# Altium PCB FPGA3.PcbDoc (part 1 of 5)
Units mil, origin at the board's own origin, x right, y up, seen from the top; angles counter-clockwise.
Board outline 4000 x 2750 mil, 12 copper layers (Top Layer, Plane1, MidLayer1, Plane2, MidLayer2, Plane3, Plane4, MidLayer 3, Plane5, MidLayer 4, Plane6, Bottom Layer), stack 57.29 mil thick; 420 components, 368 nets, 1889 pads, 1236 vias.
Unrouted connection lines stored in the file: 1.
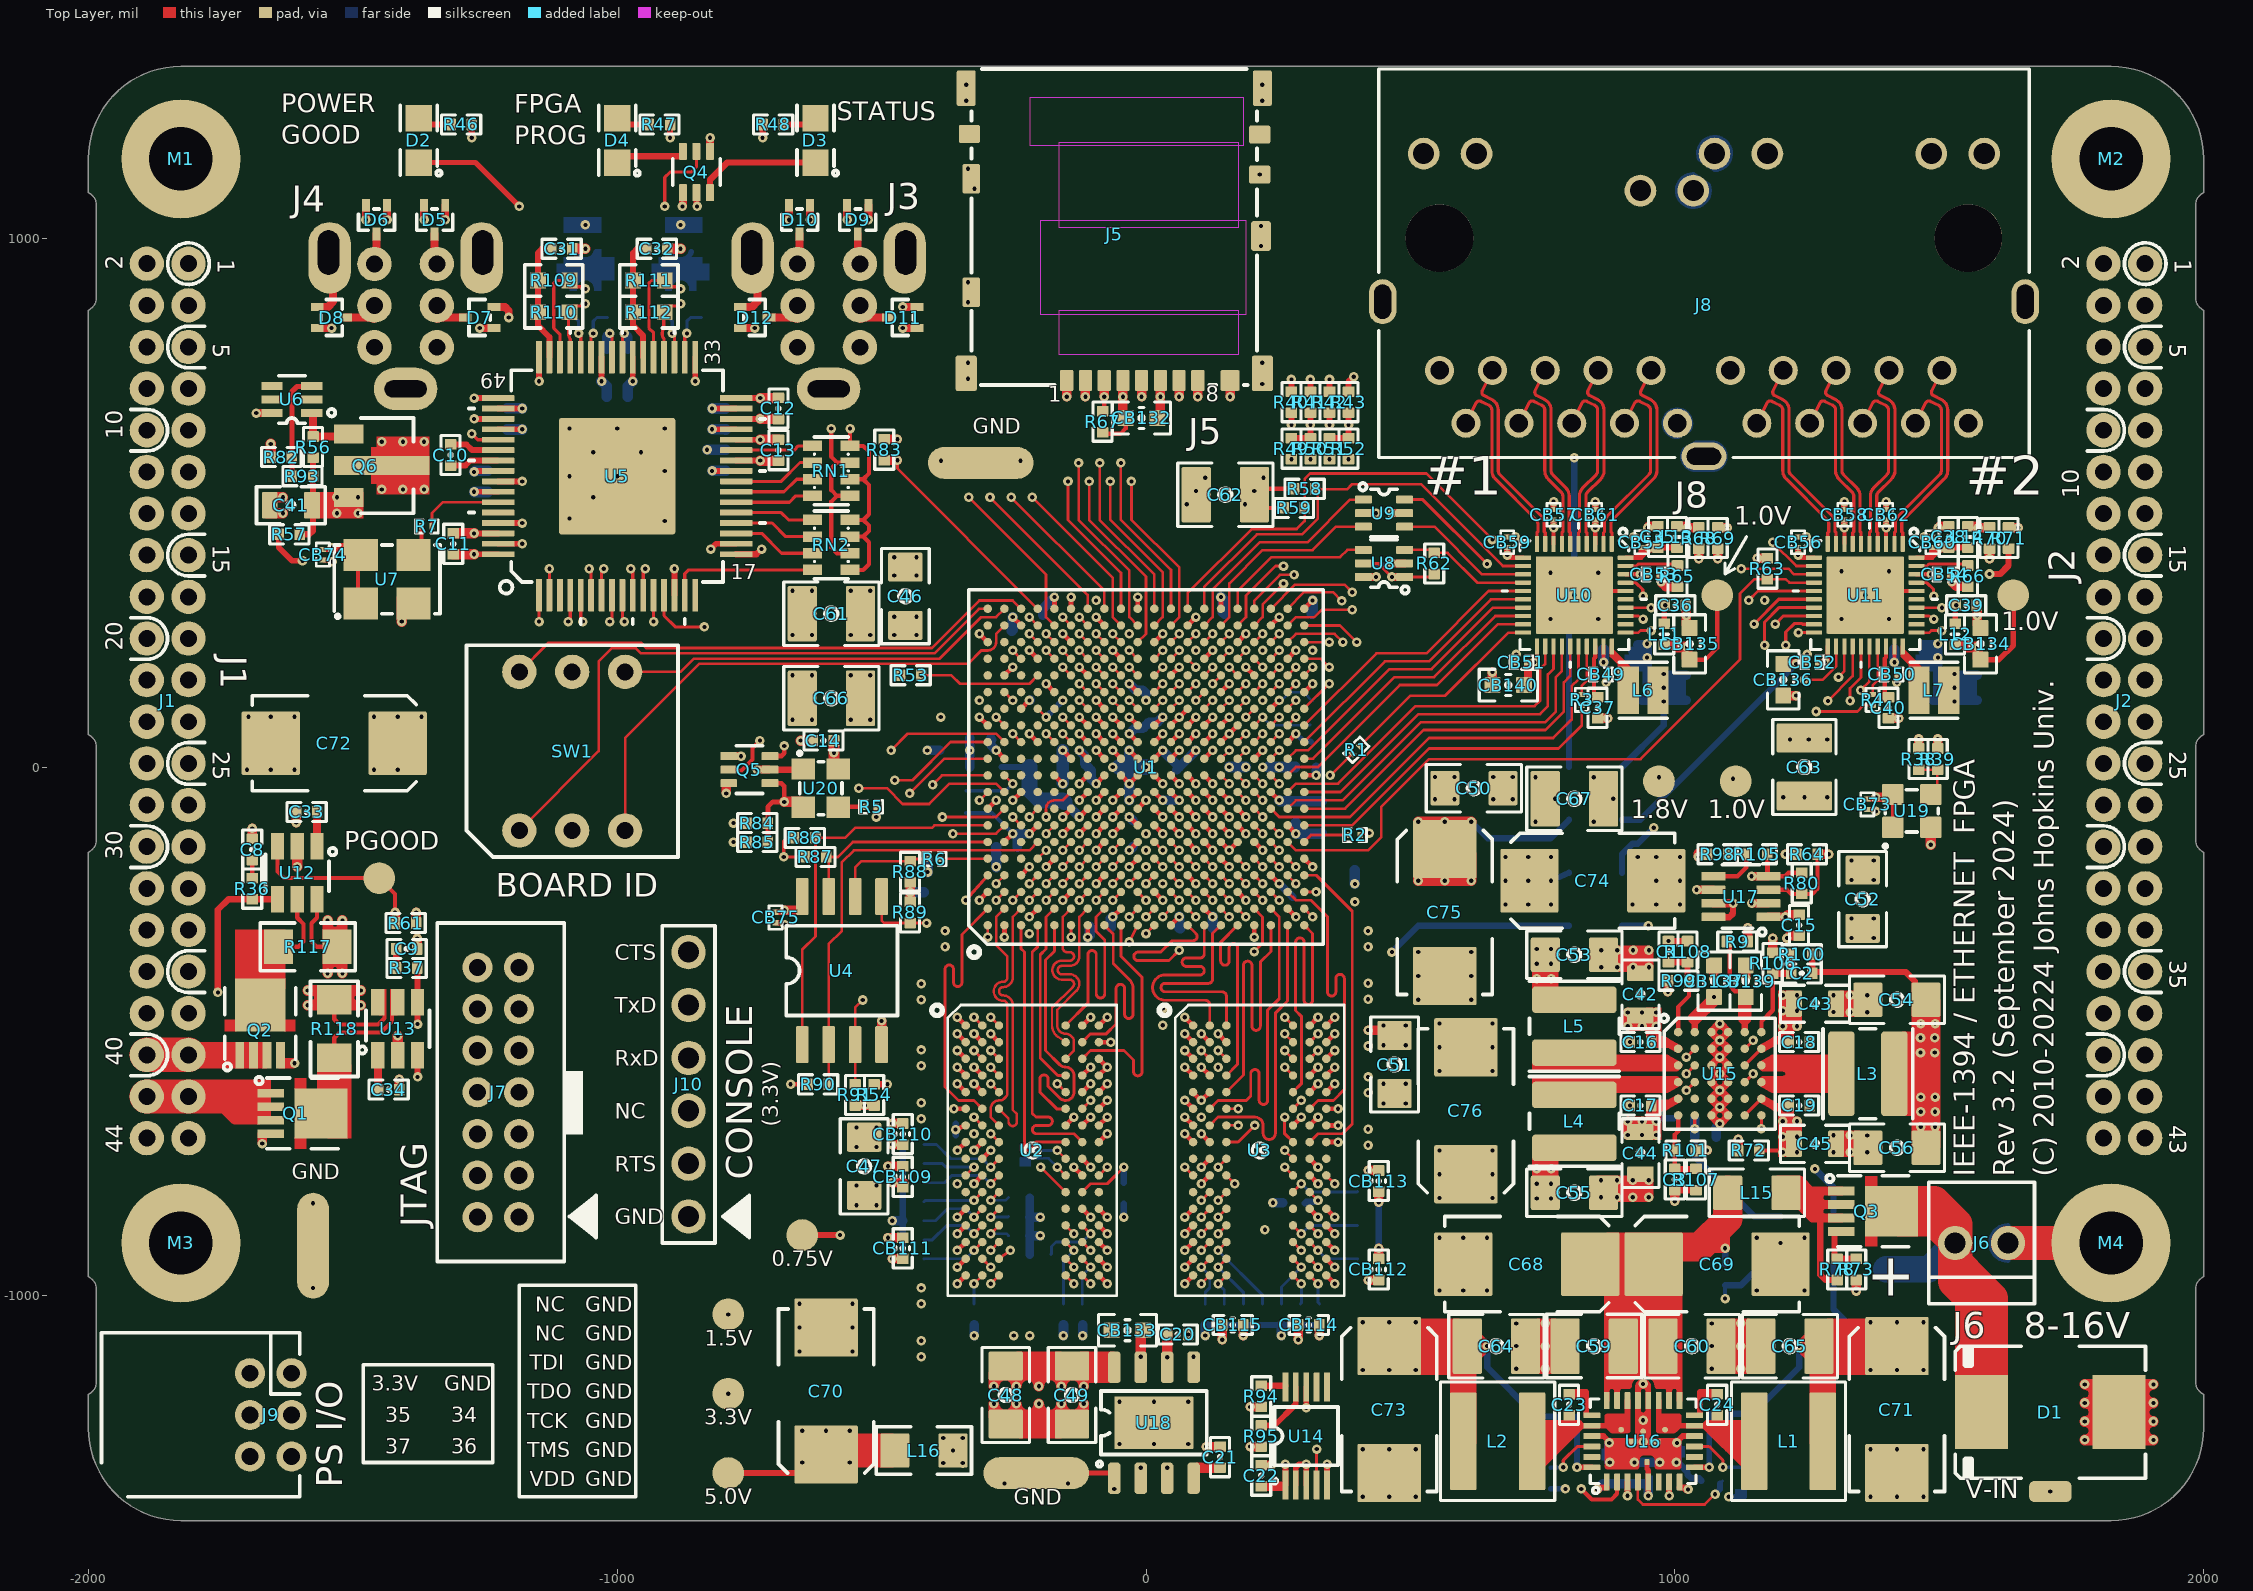
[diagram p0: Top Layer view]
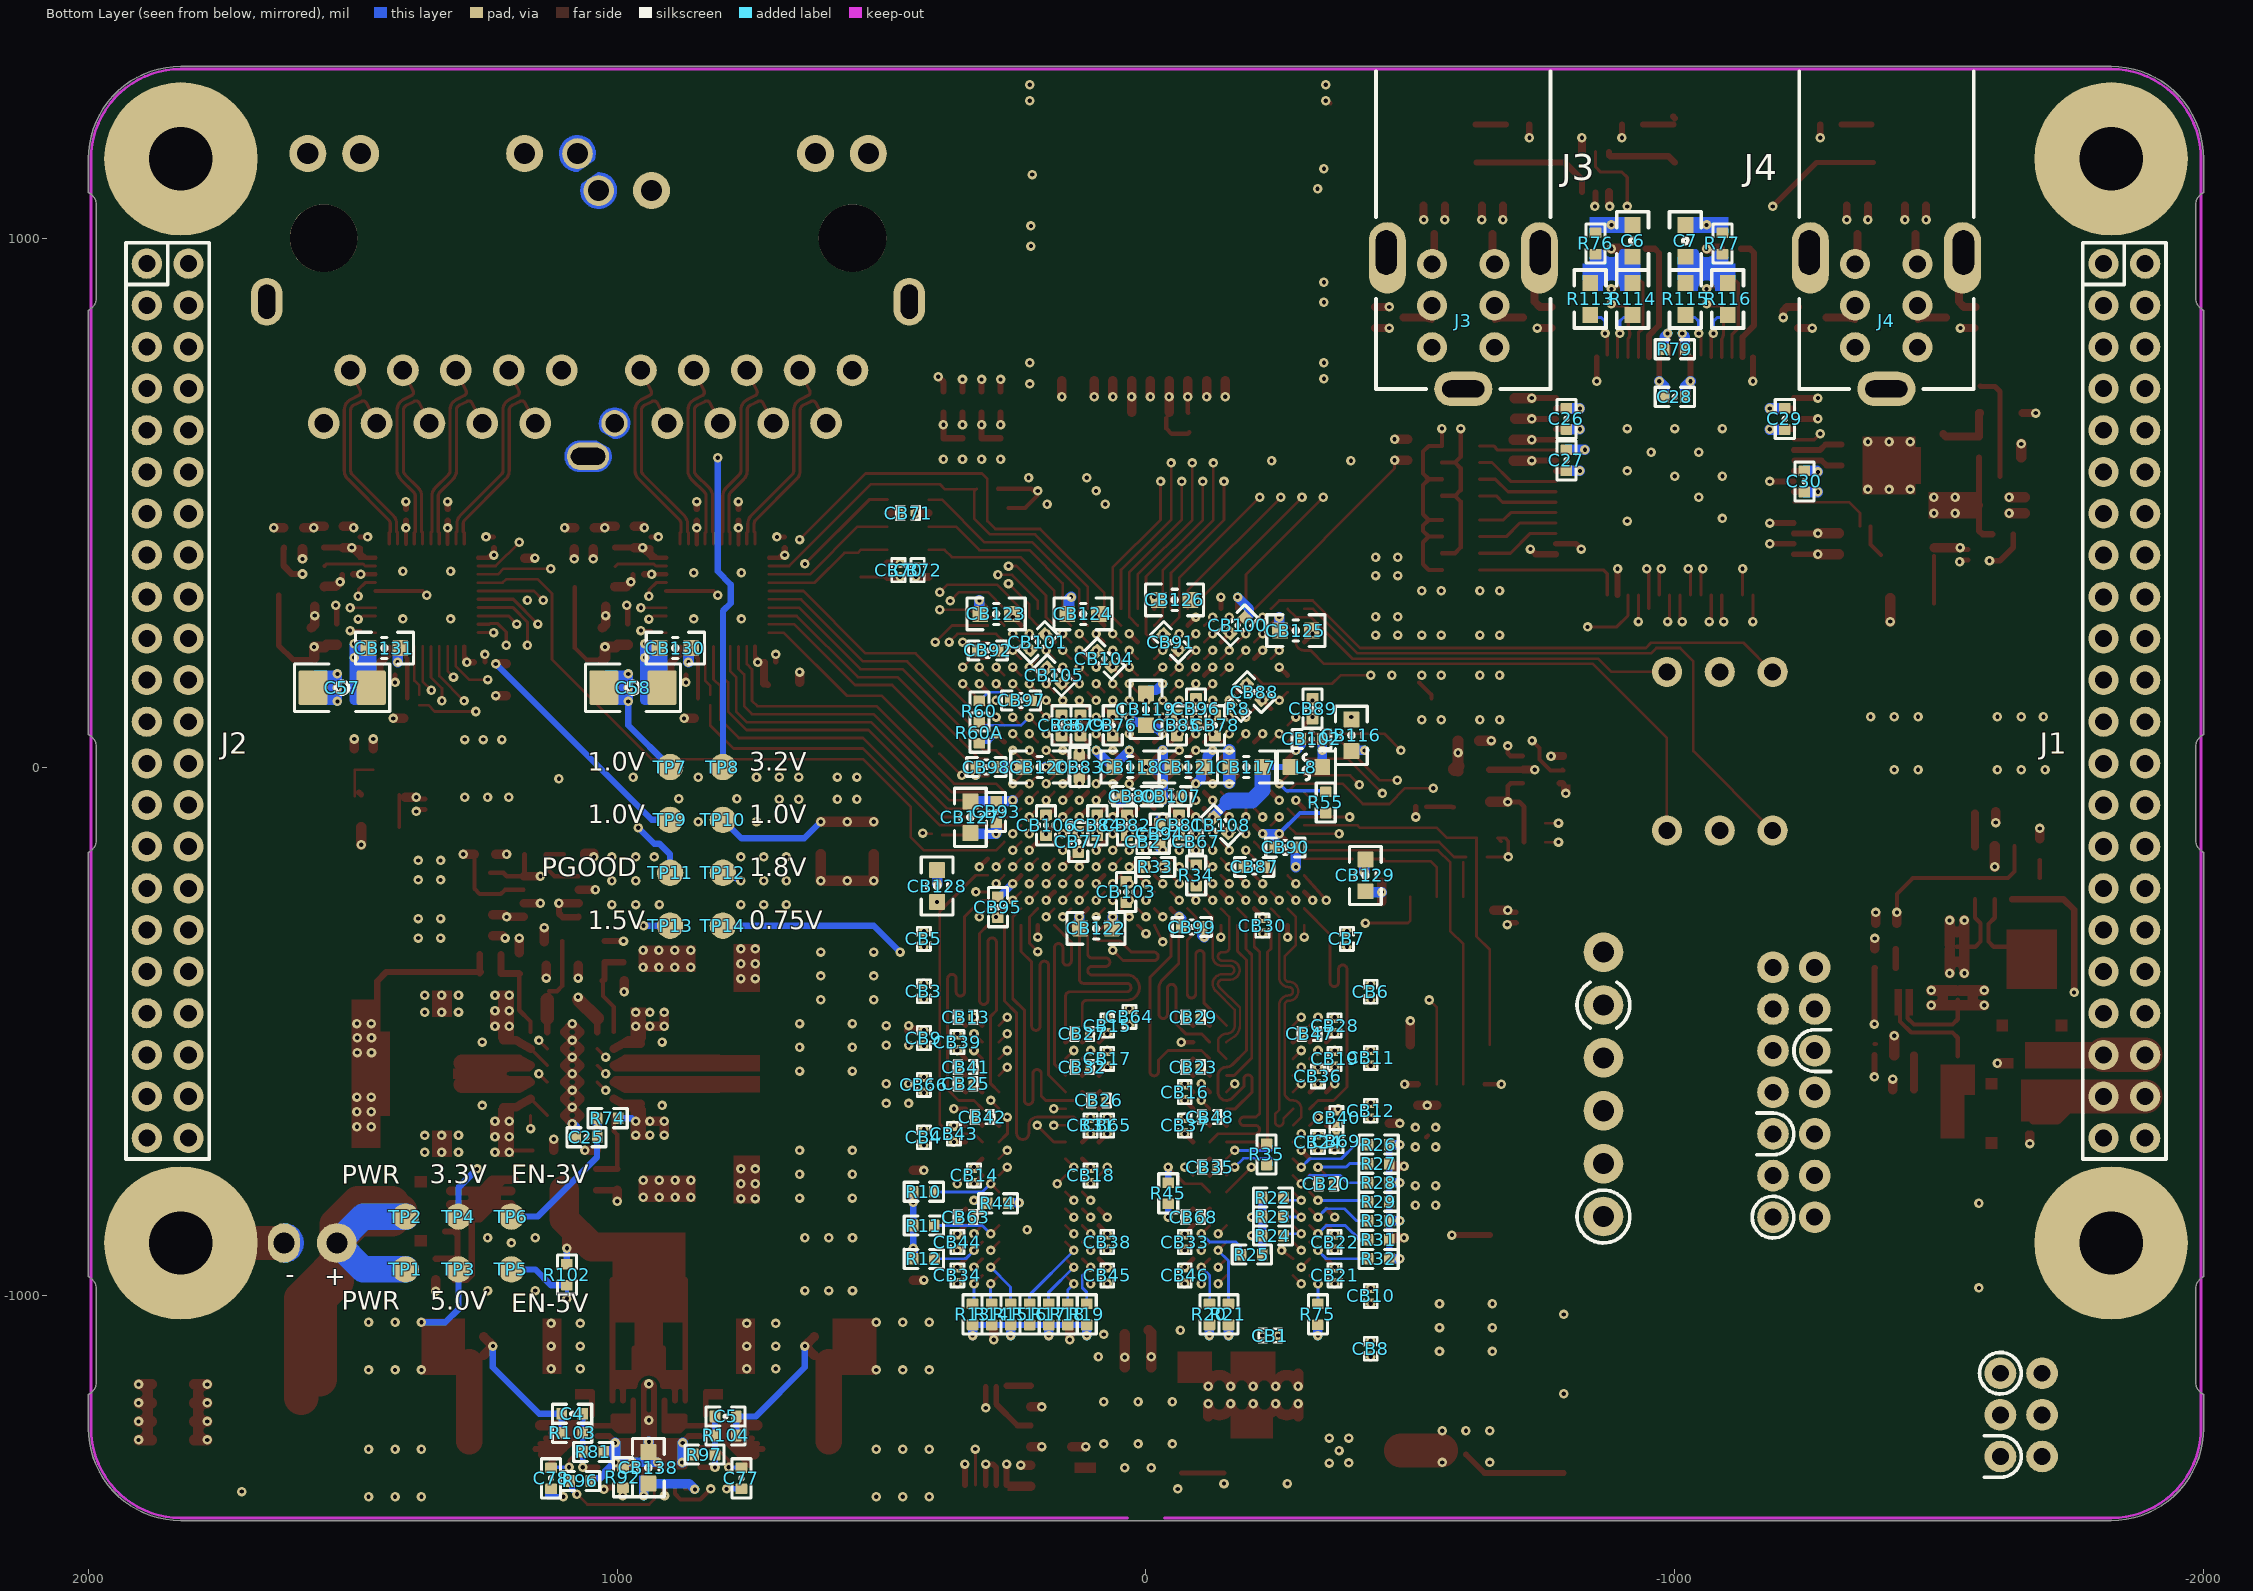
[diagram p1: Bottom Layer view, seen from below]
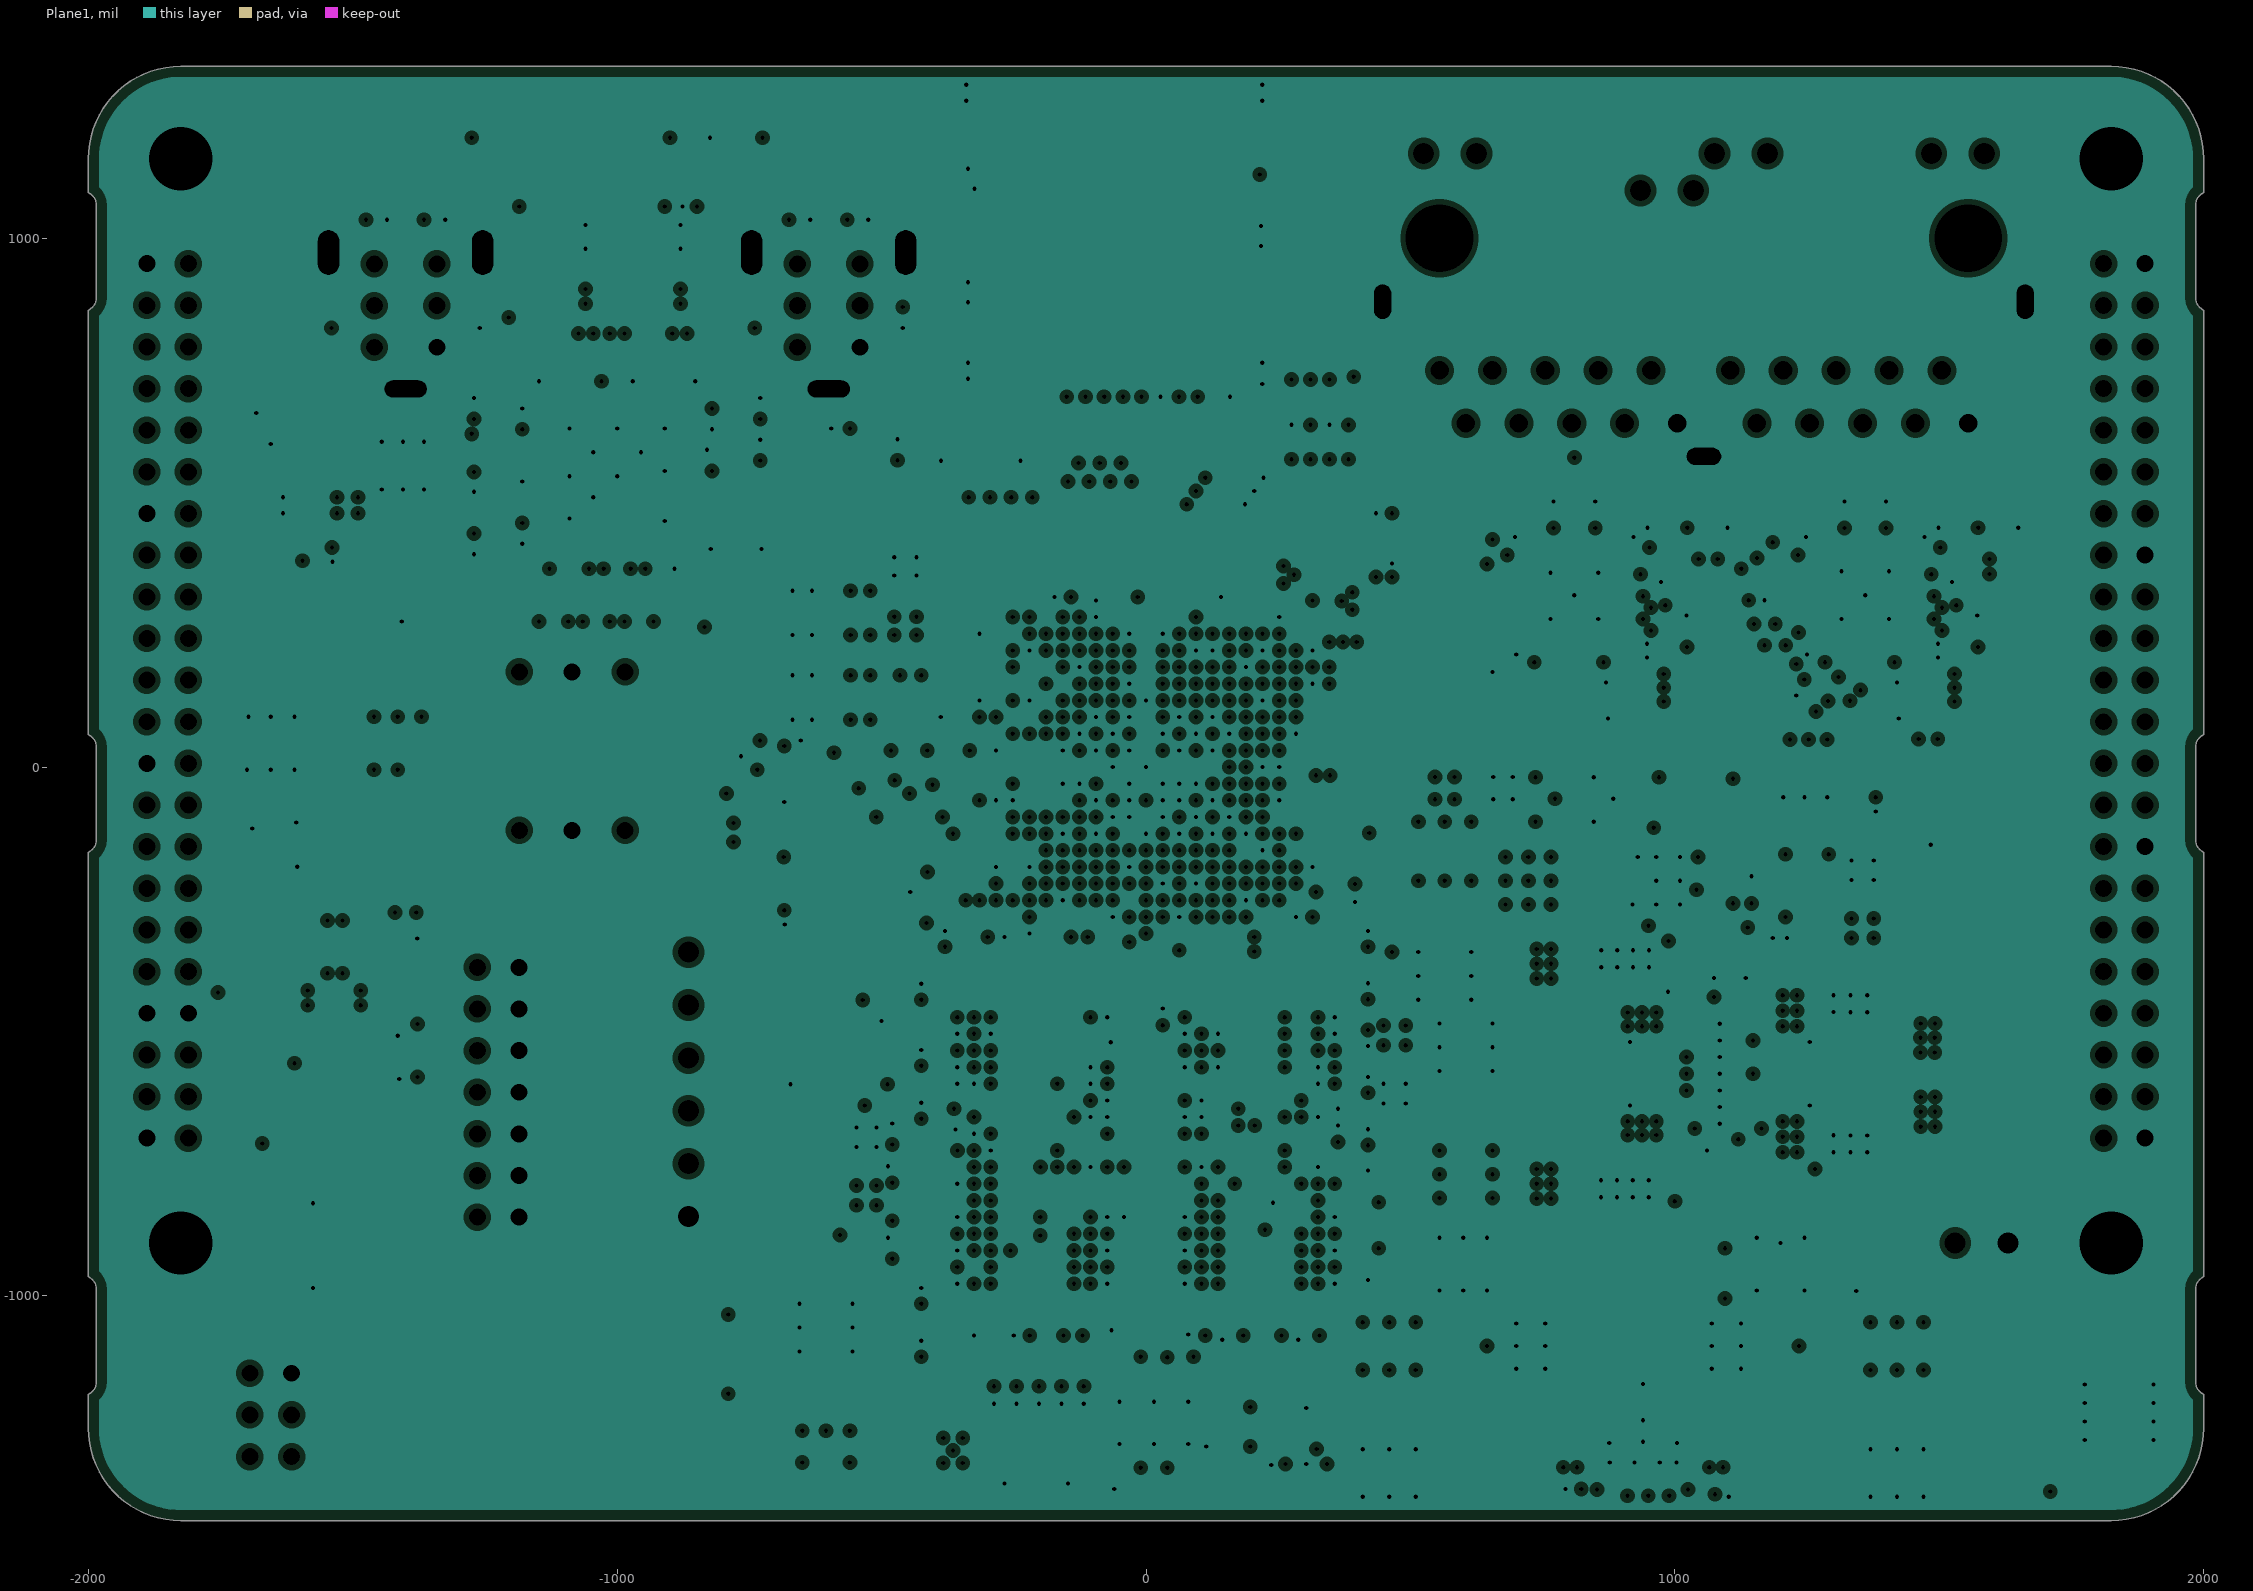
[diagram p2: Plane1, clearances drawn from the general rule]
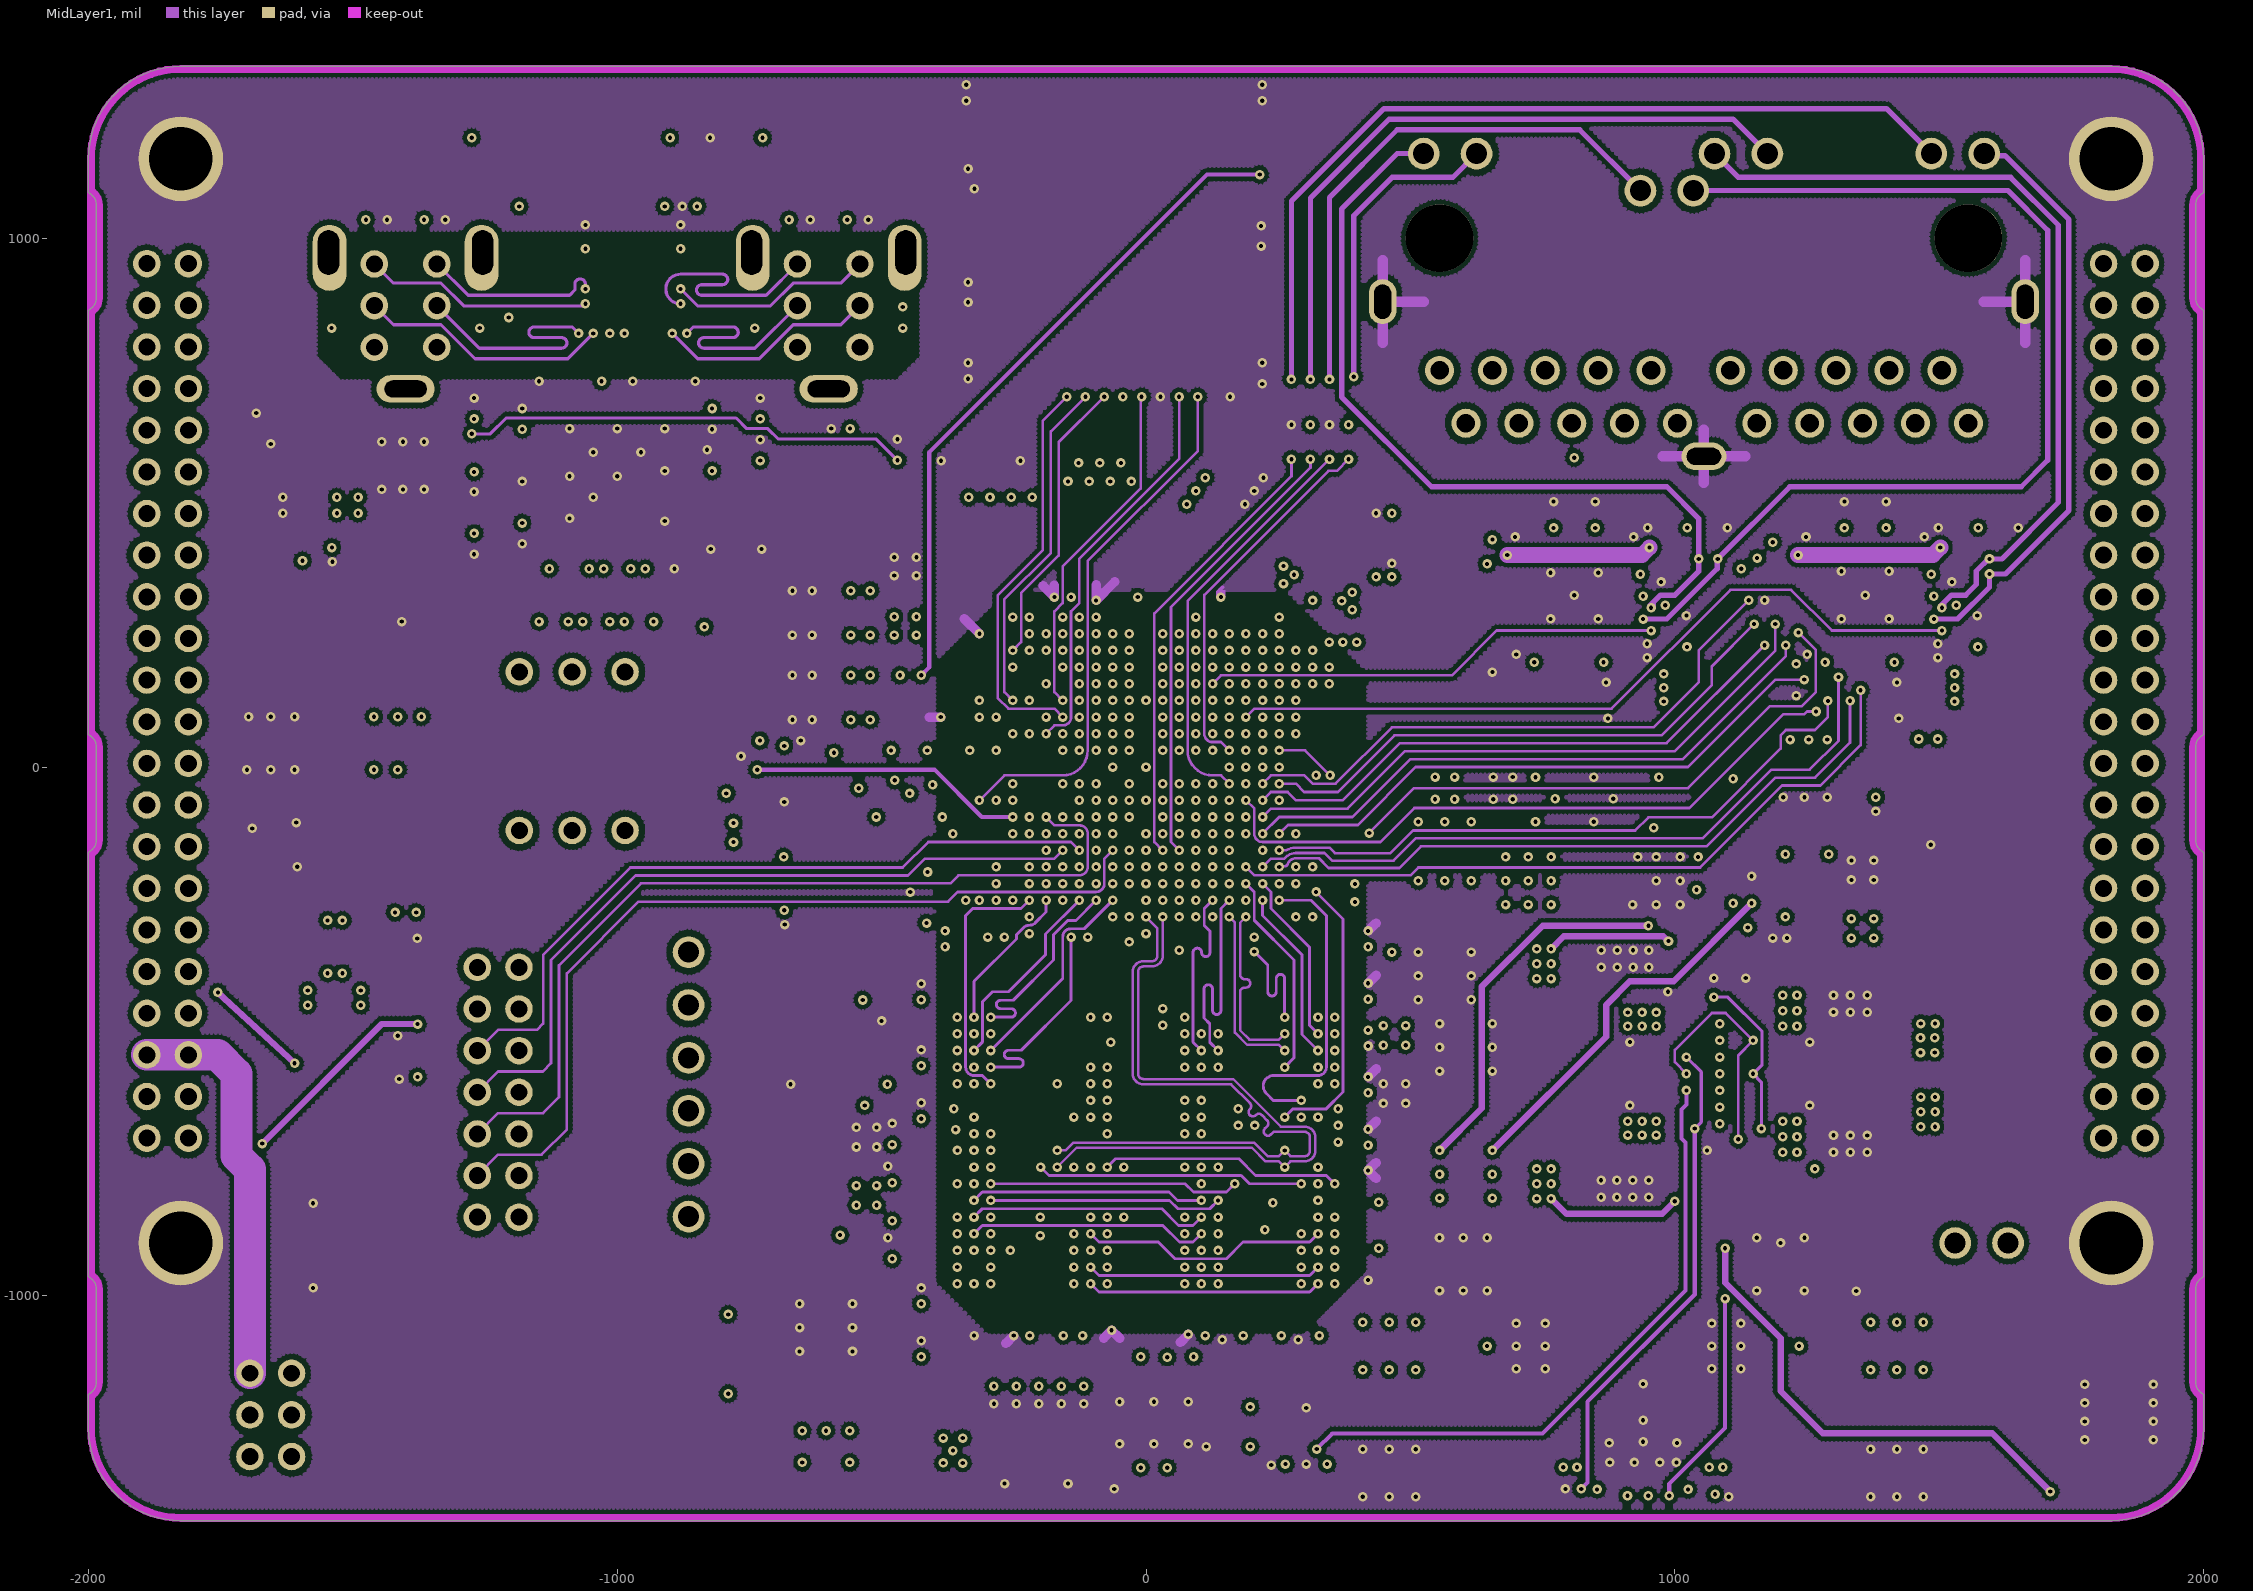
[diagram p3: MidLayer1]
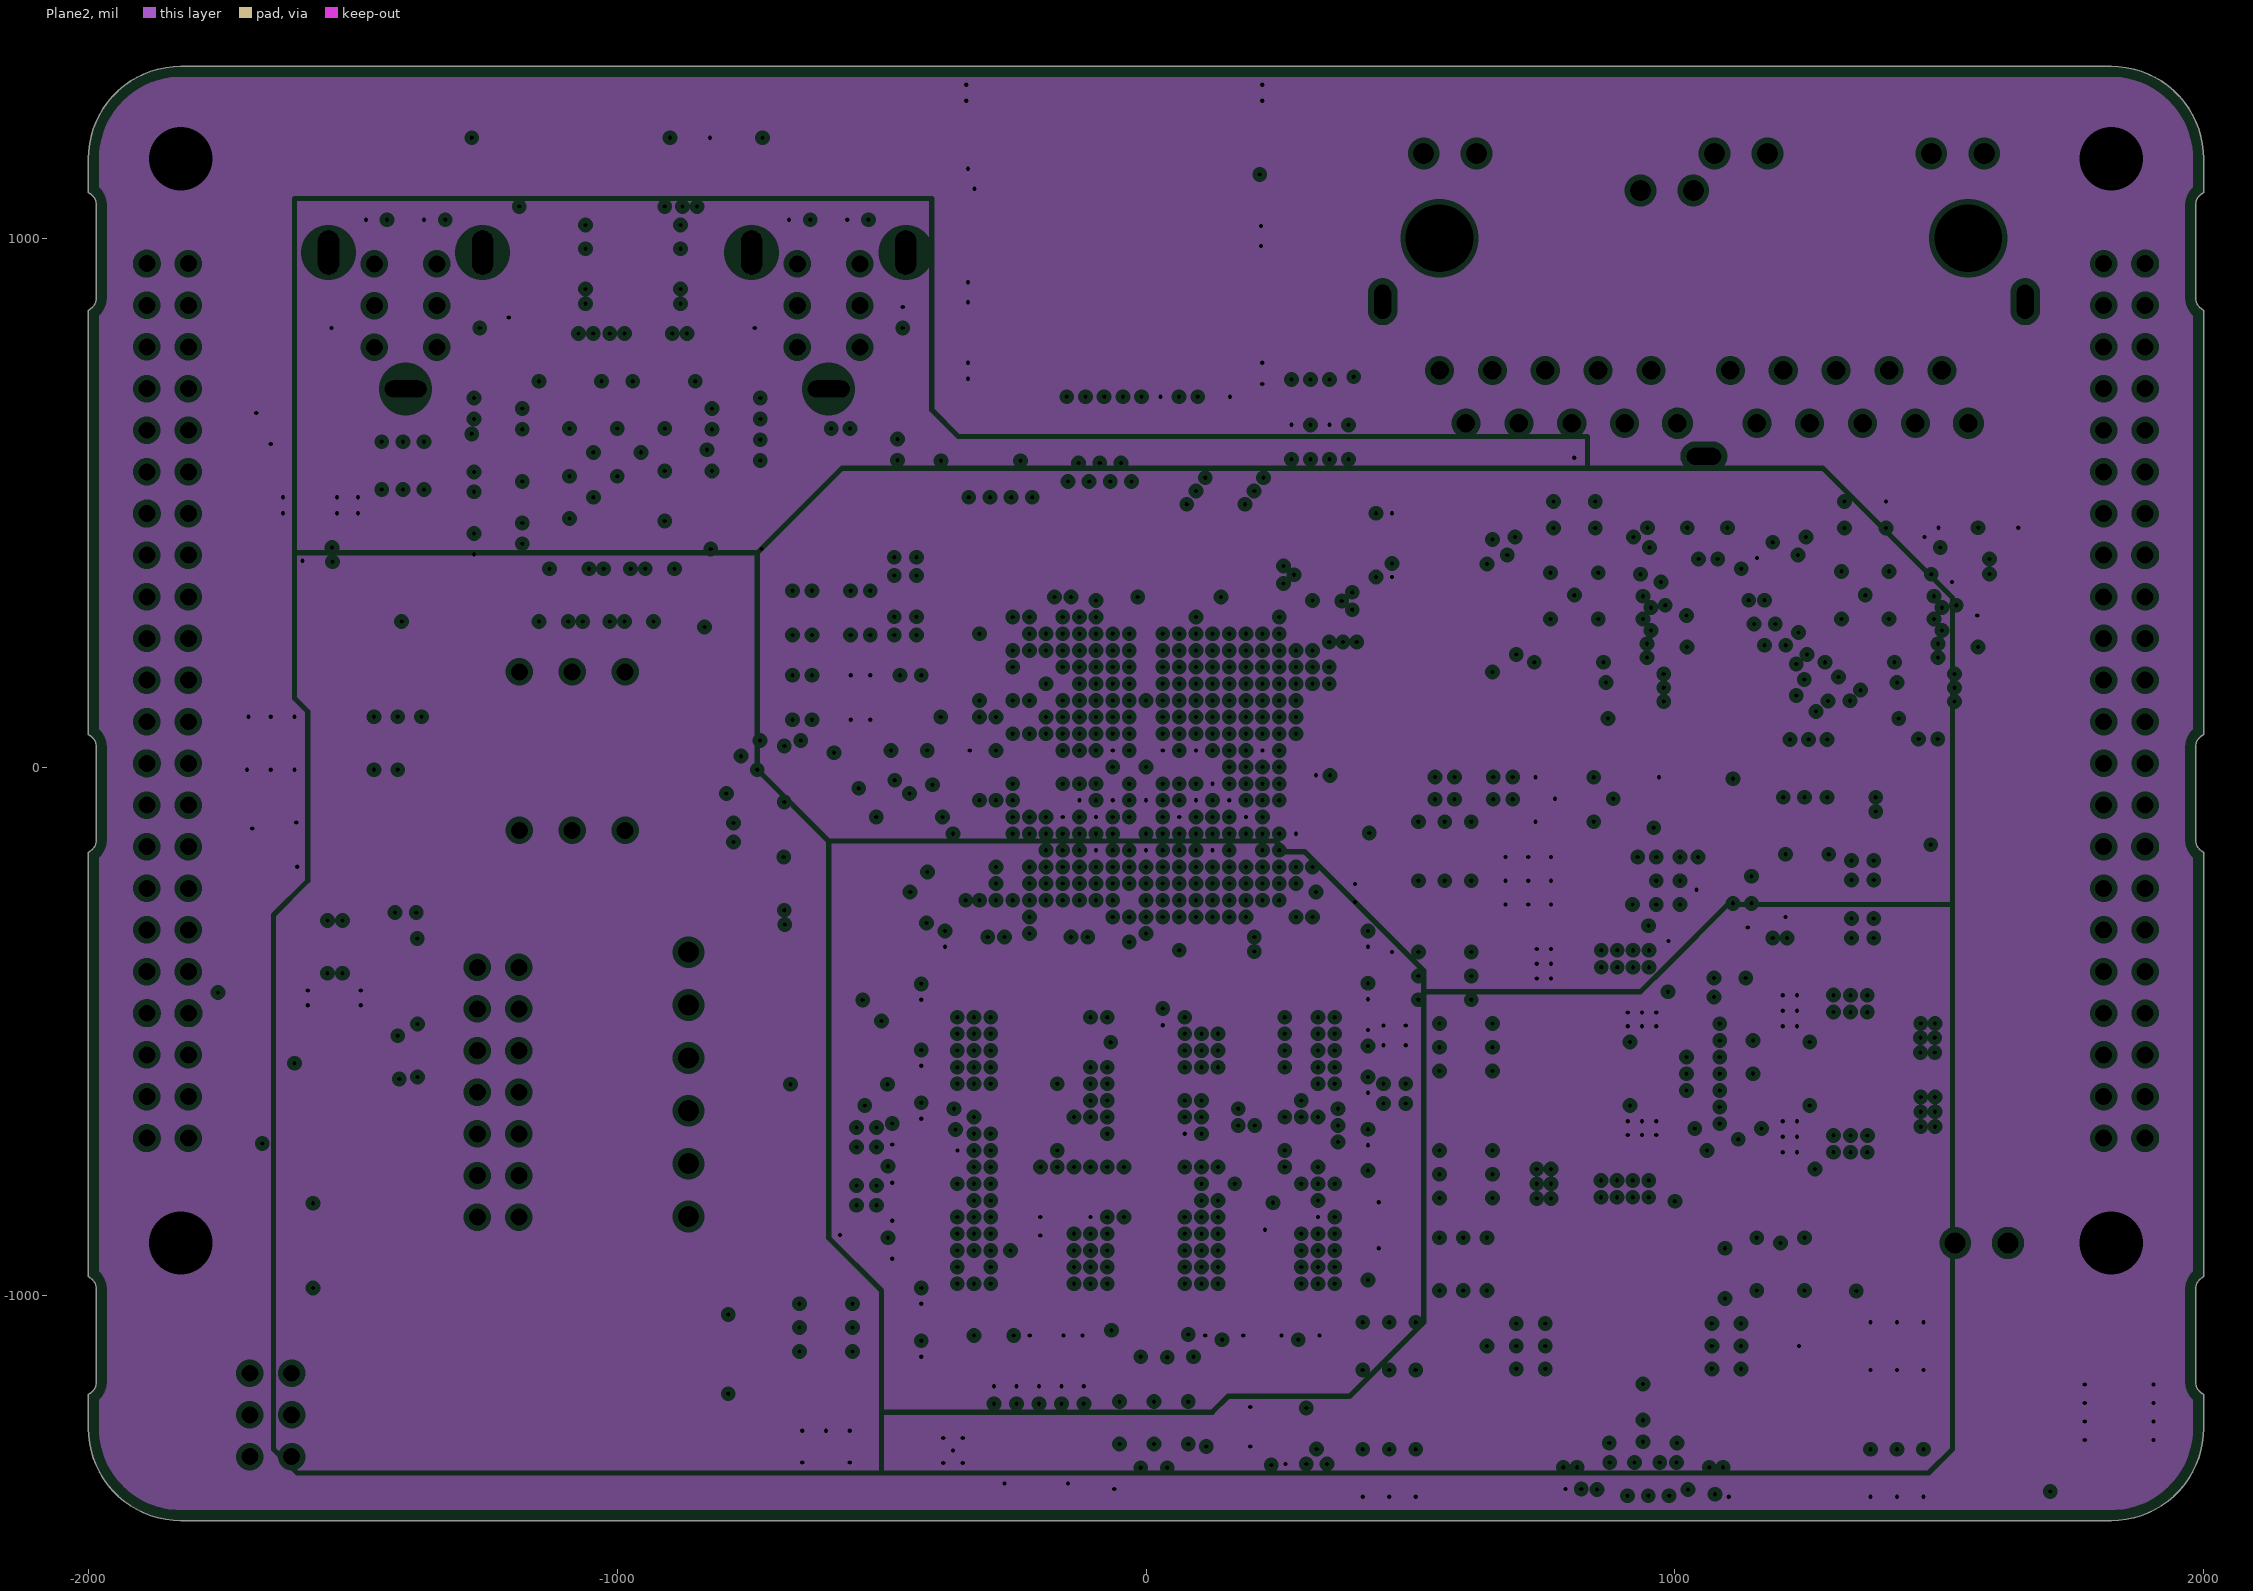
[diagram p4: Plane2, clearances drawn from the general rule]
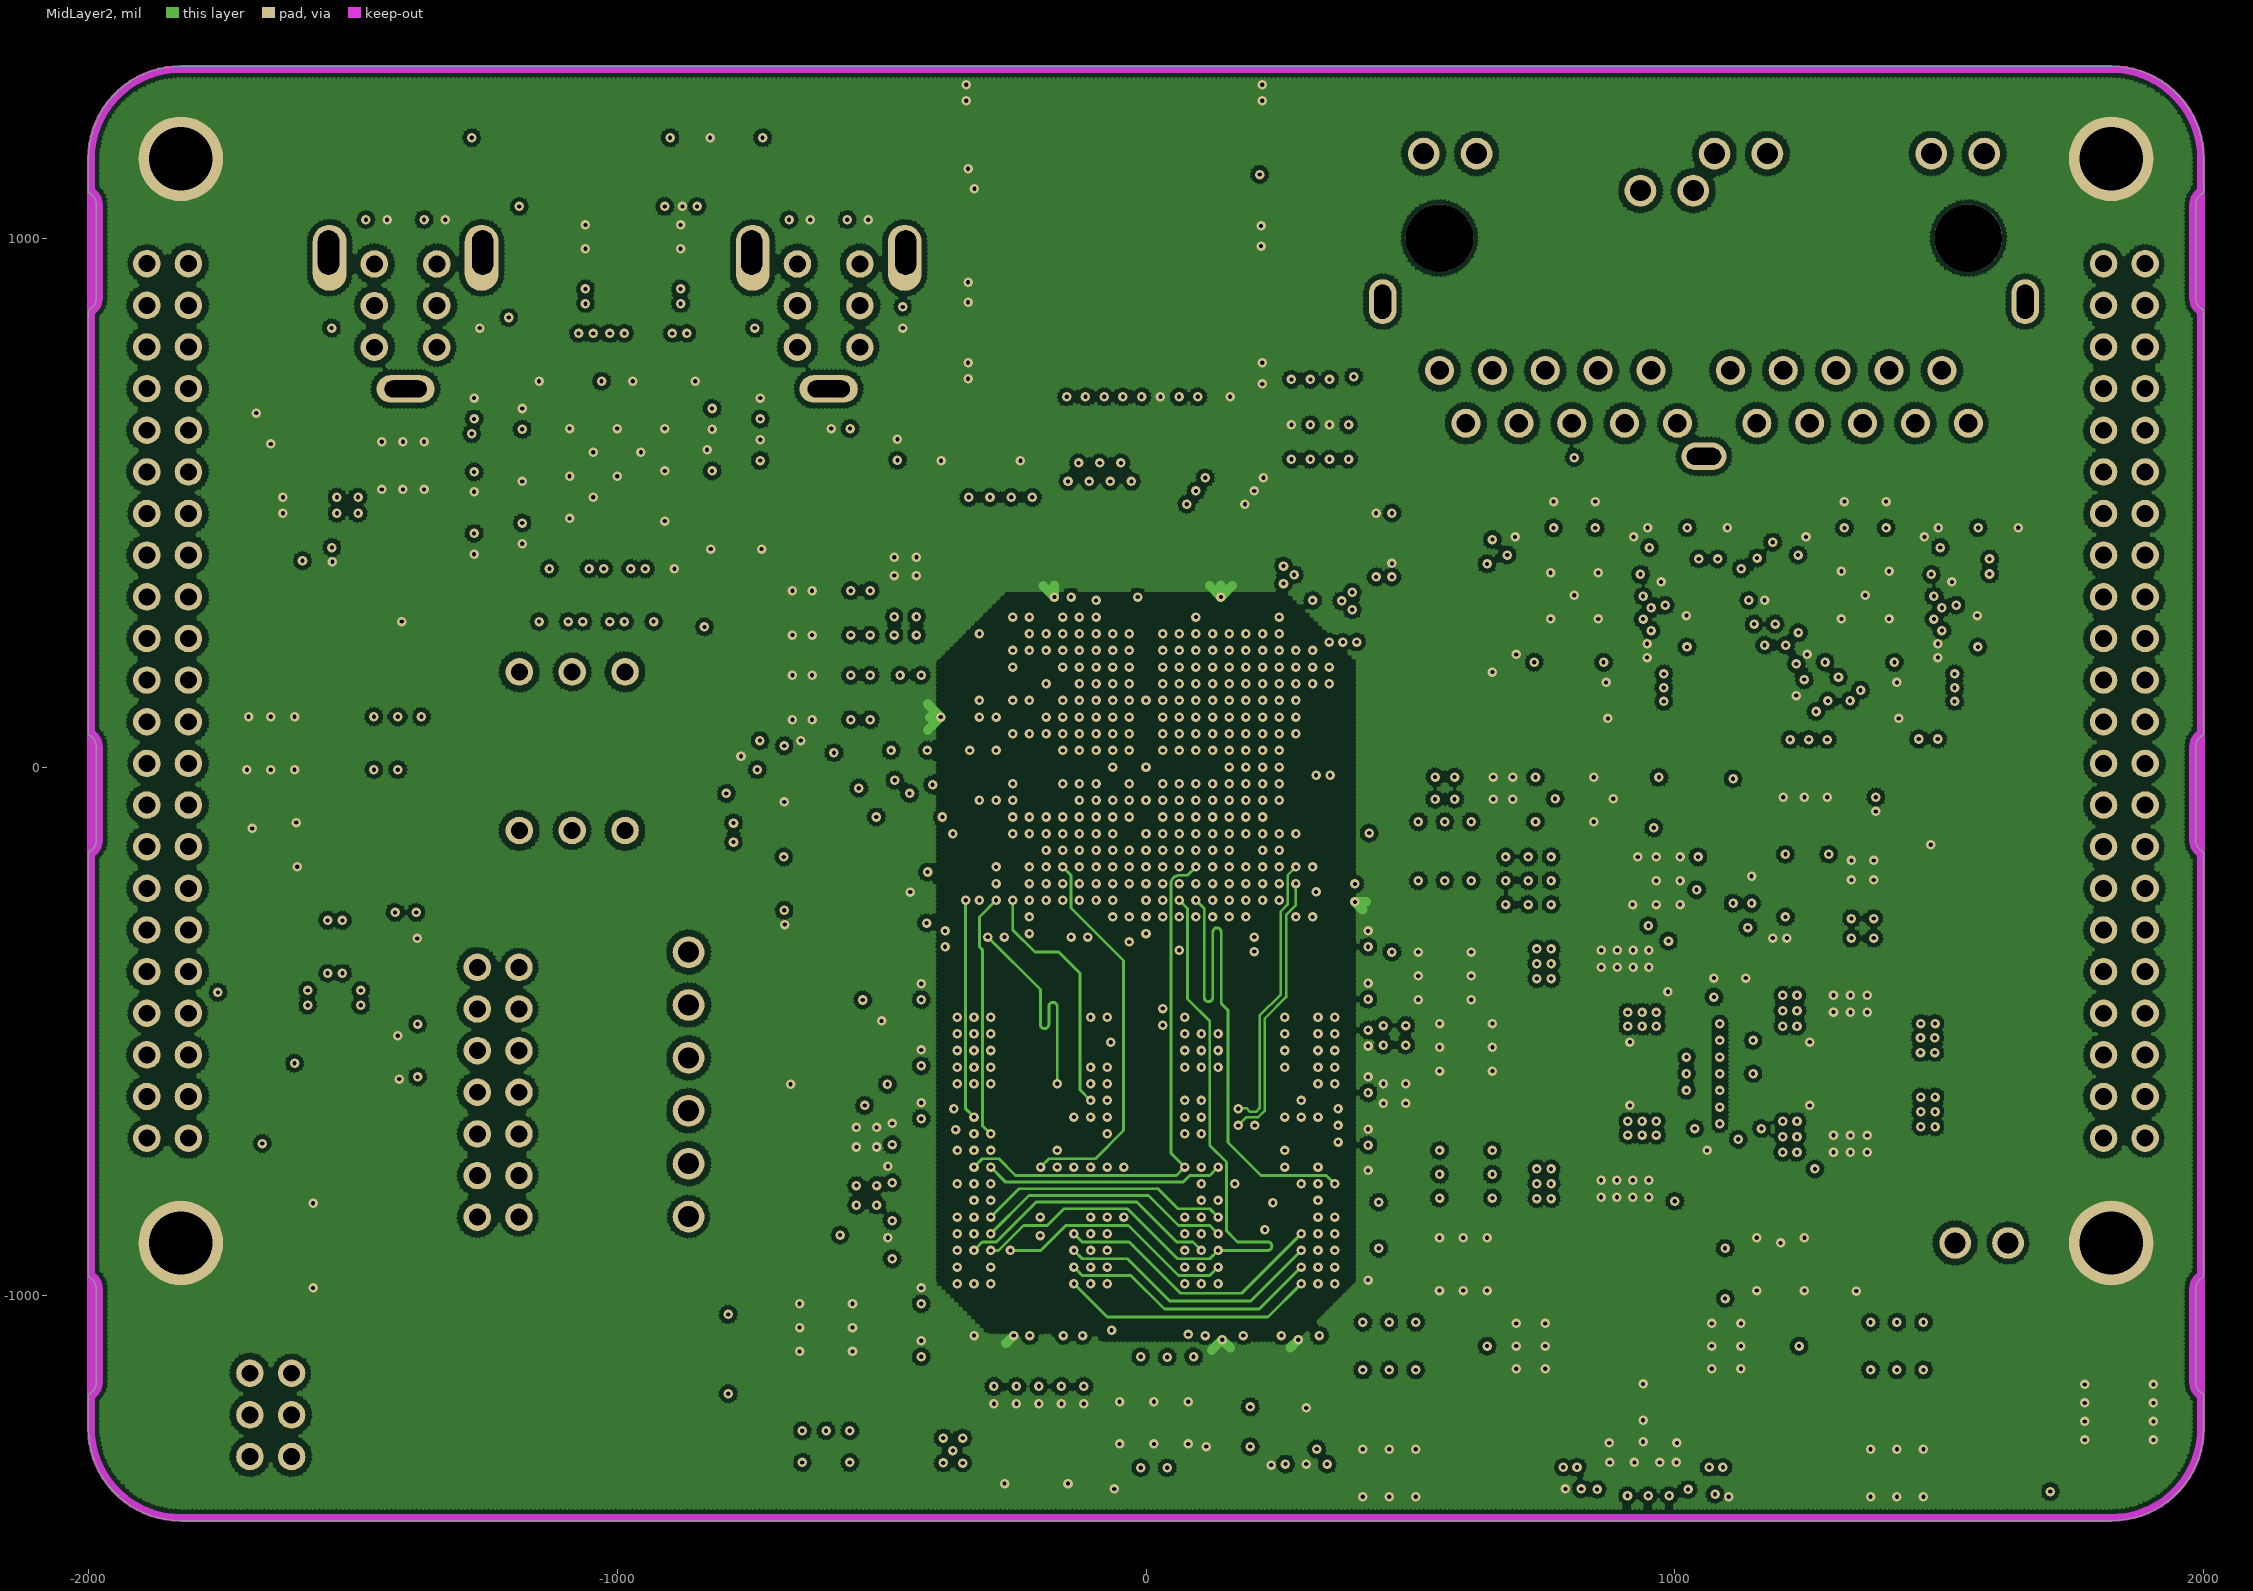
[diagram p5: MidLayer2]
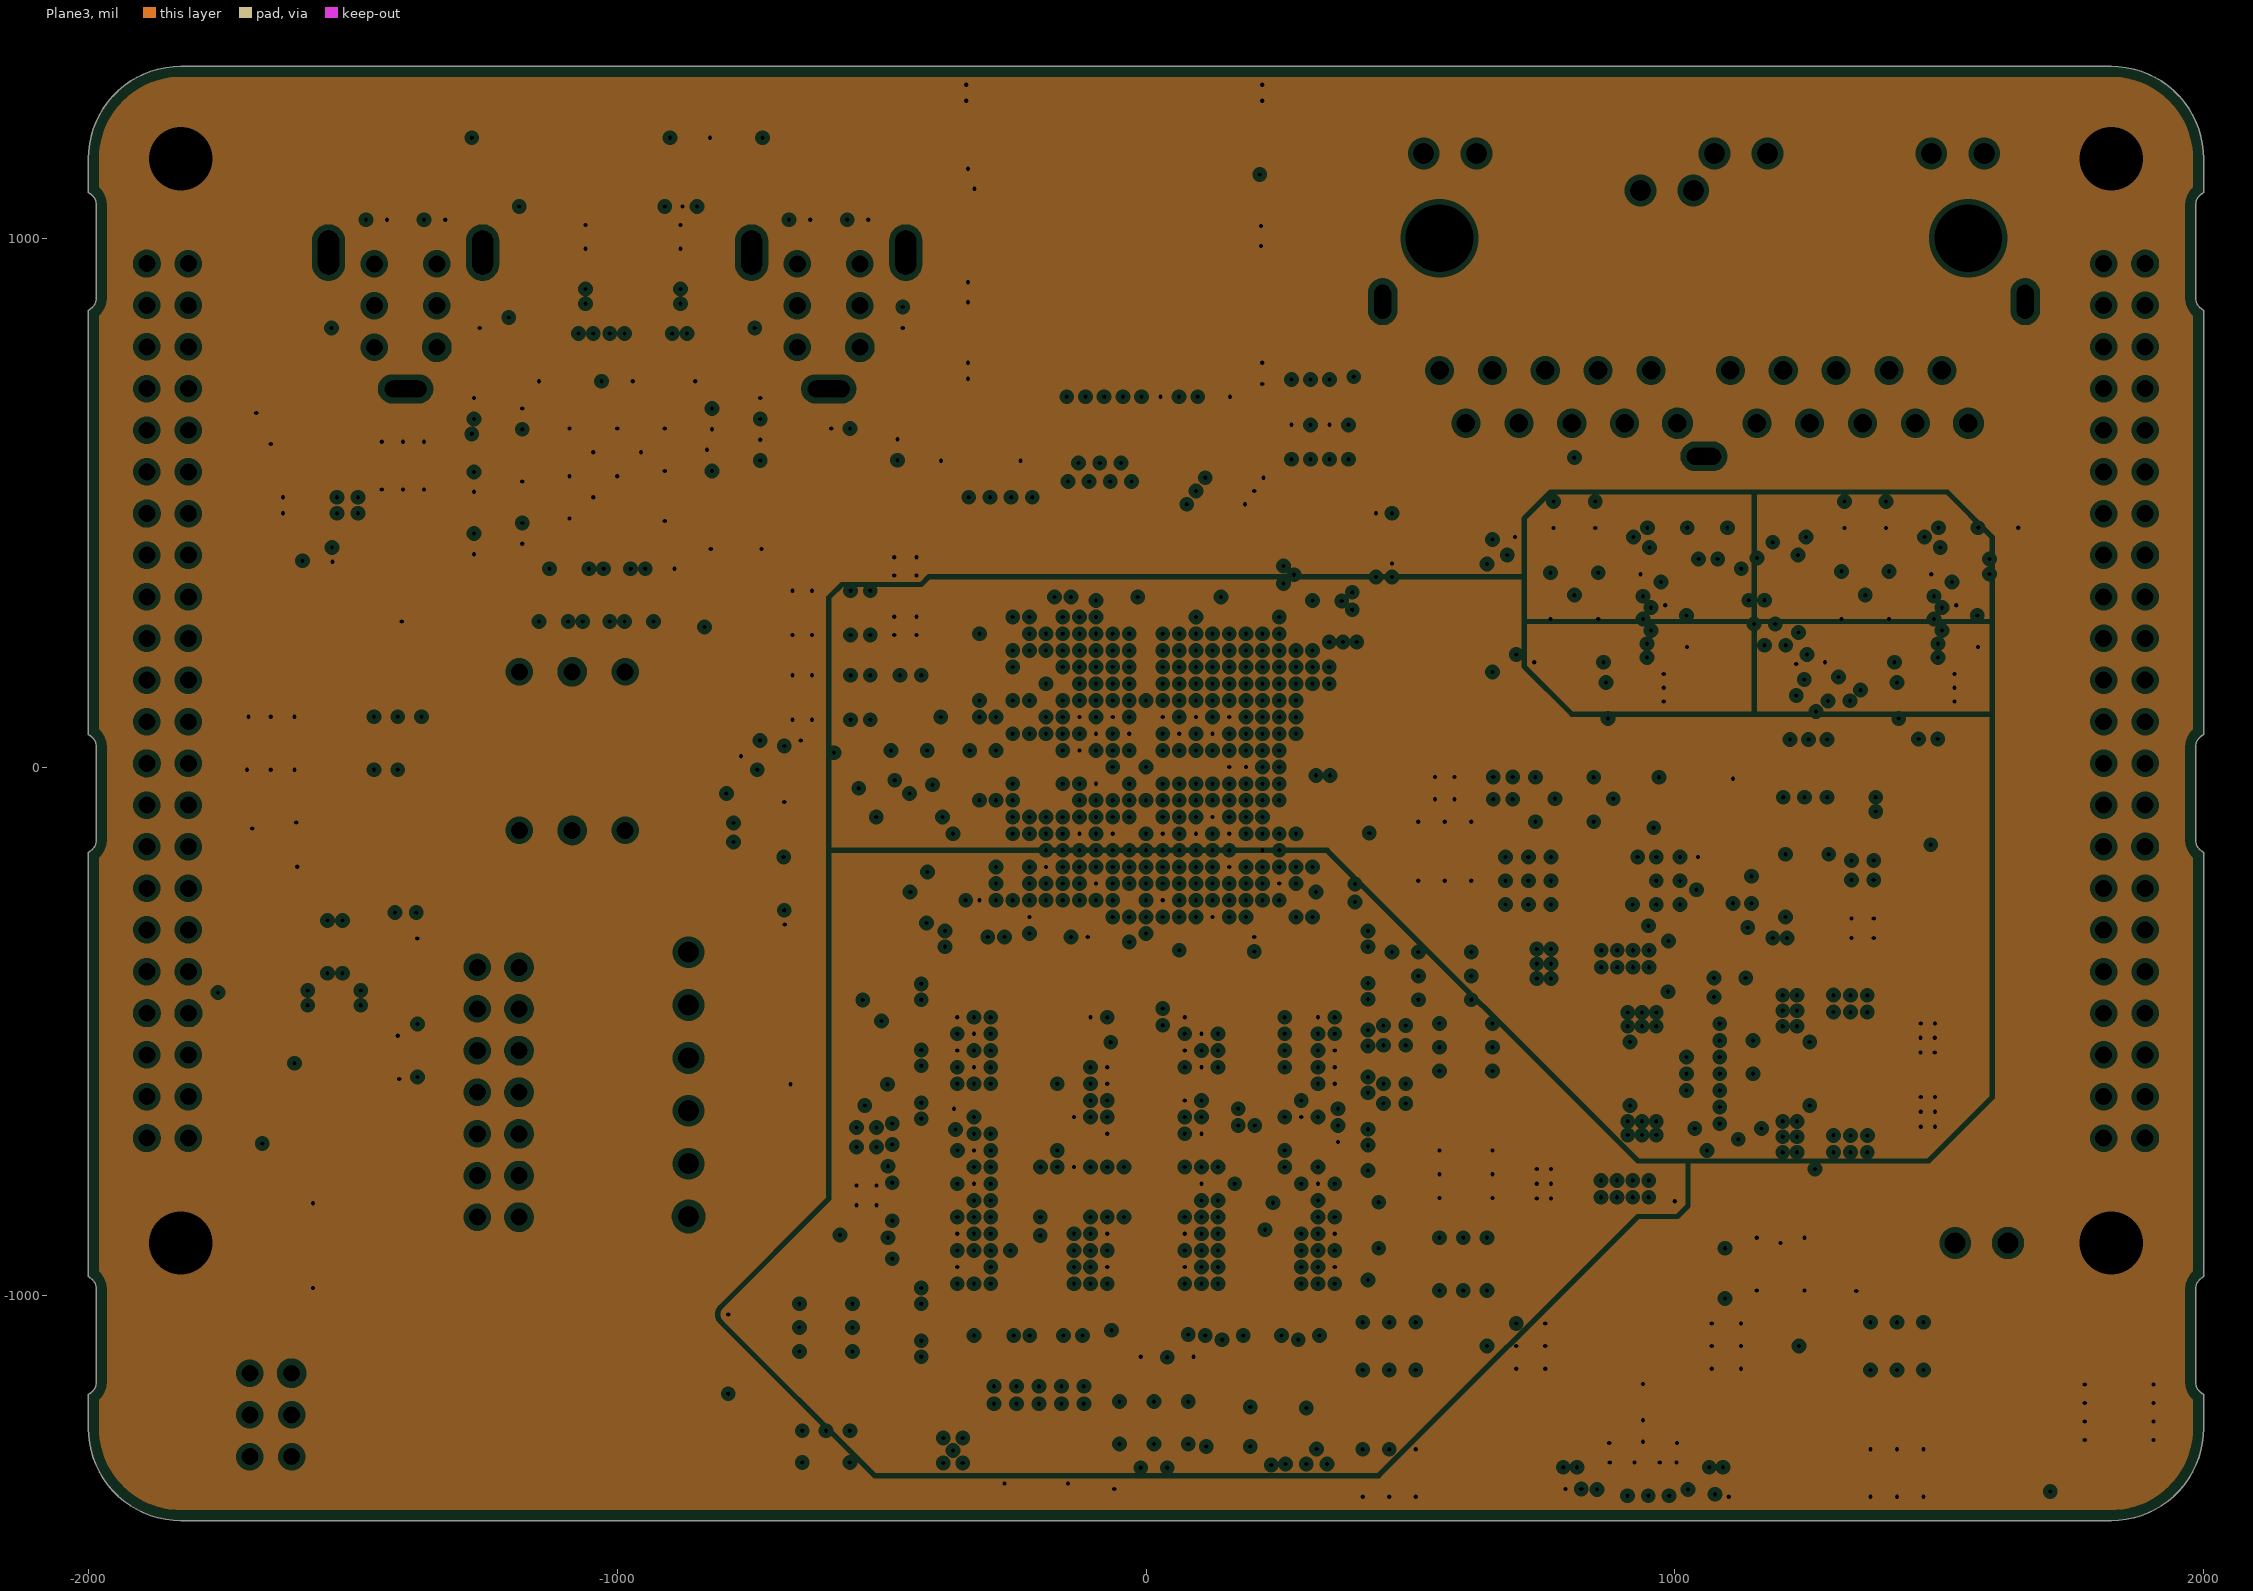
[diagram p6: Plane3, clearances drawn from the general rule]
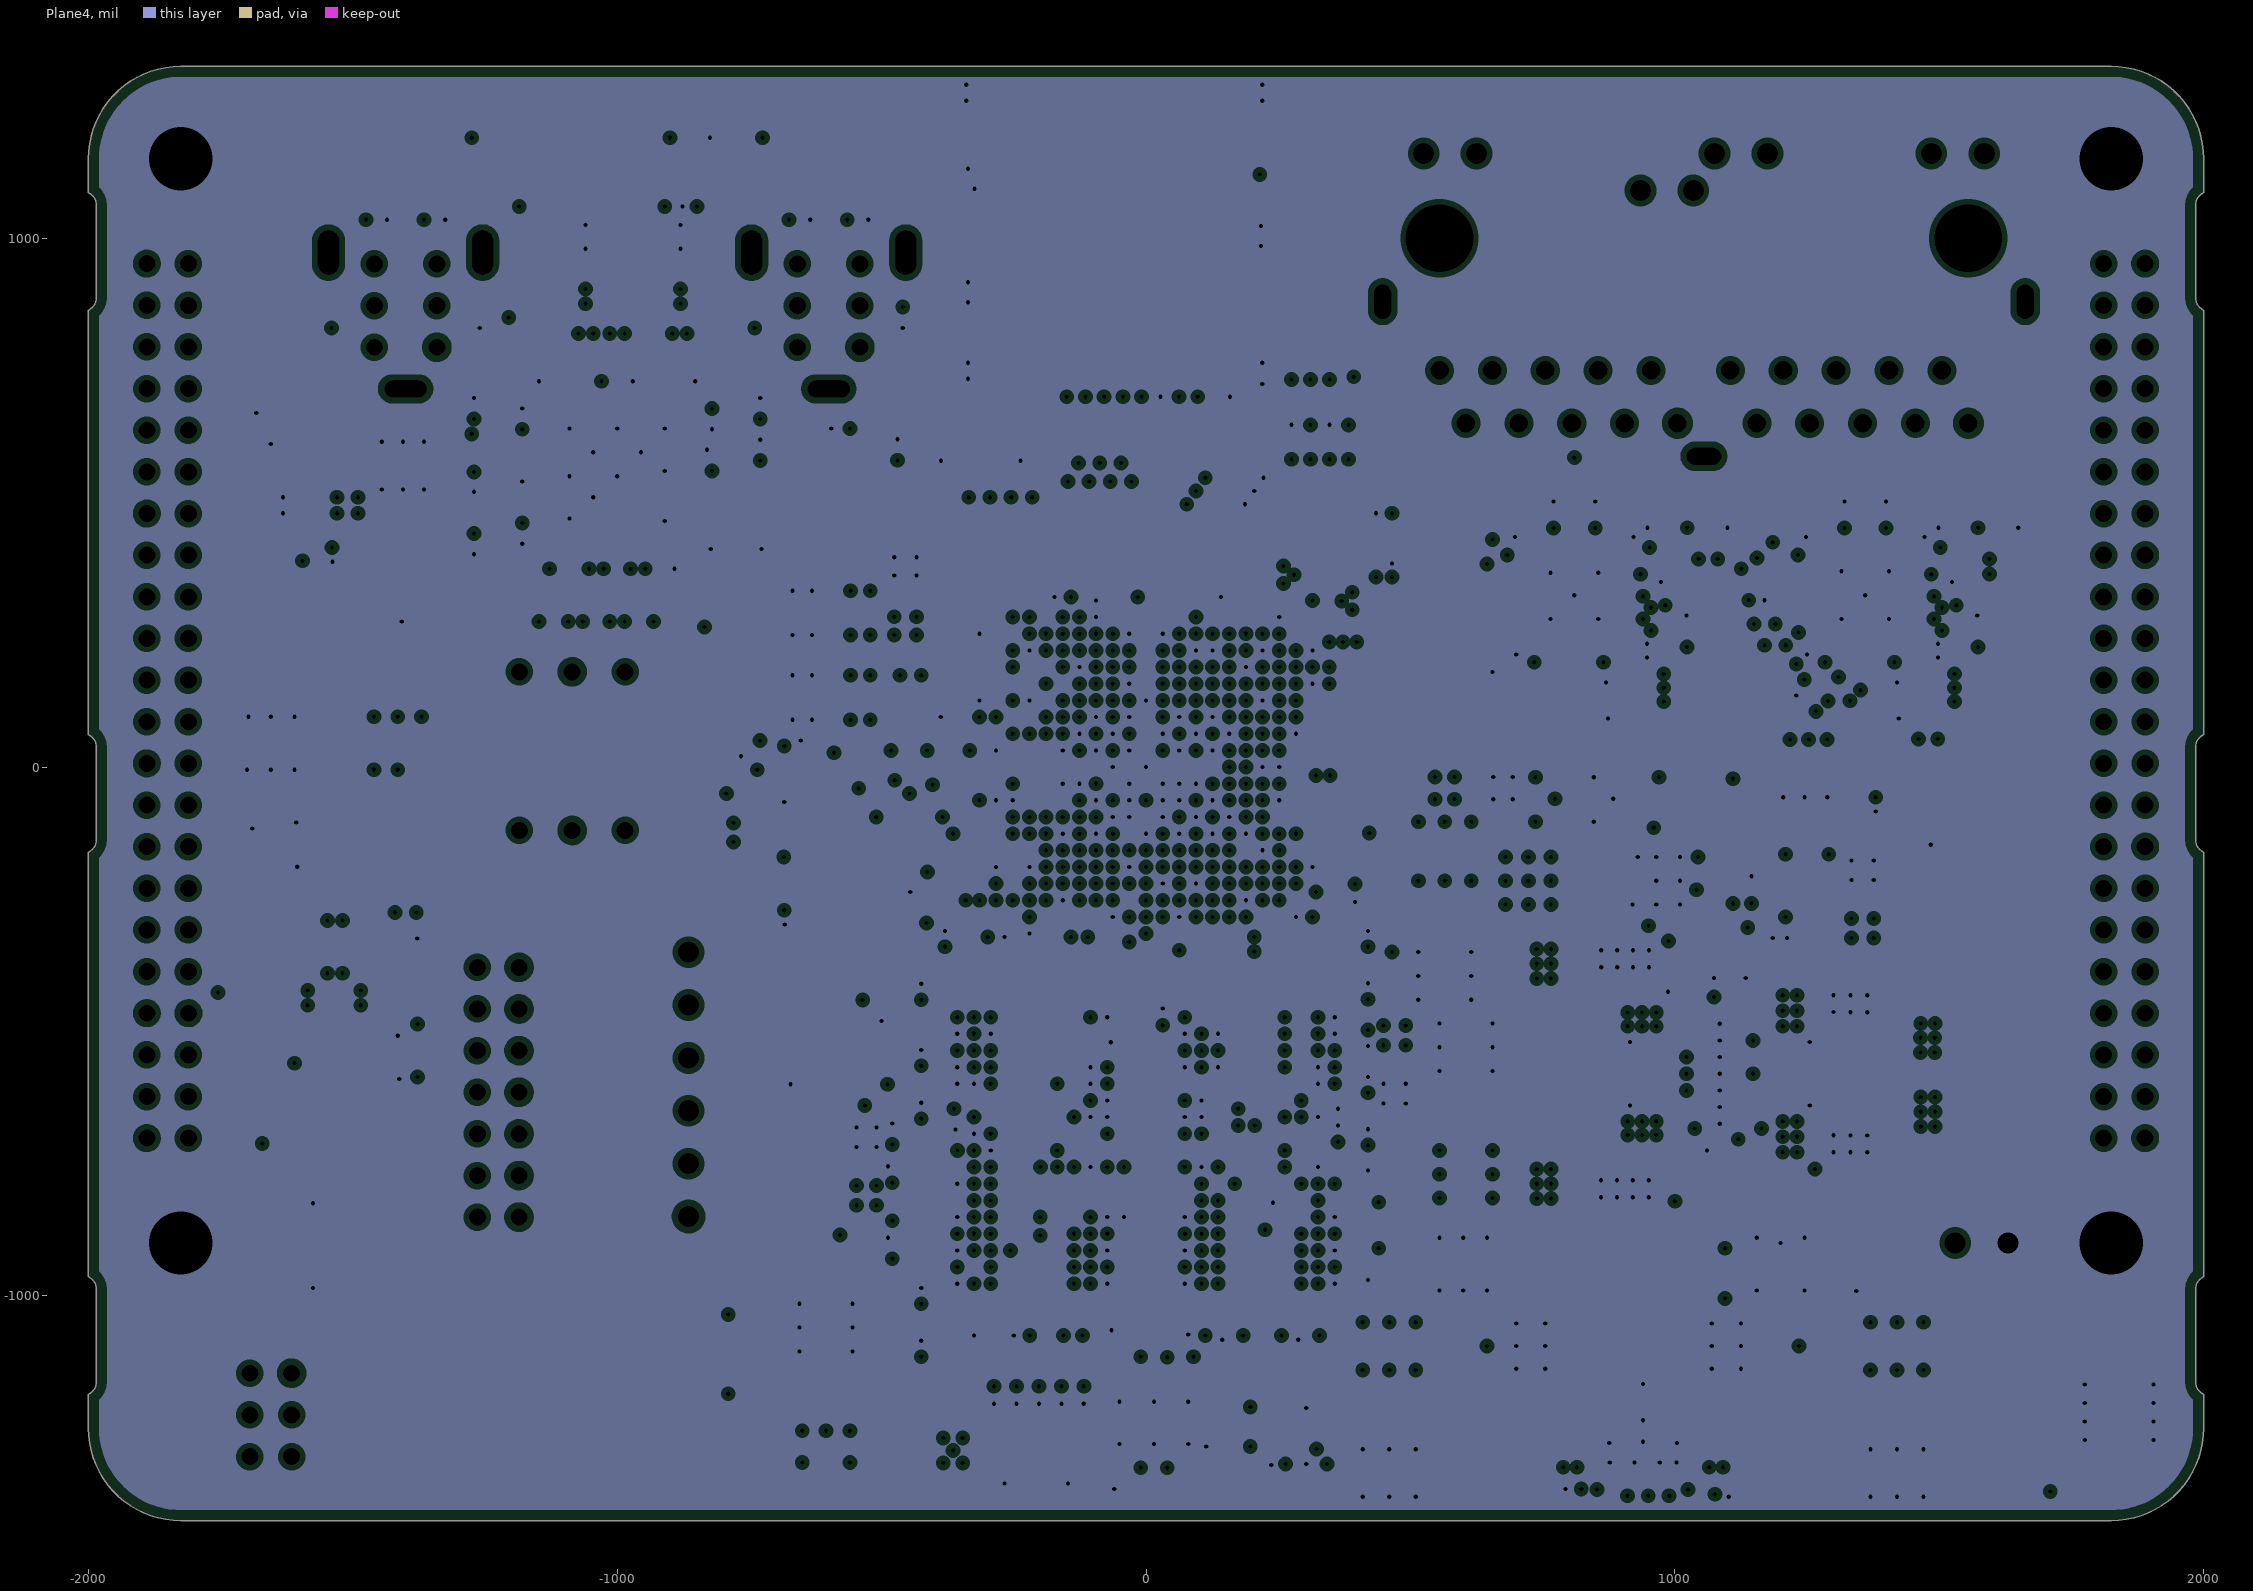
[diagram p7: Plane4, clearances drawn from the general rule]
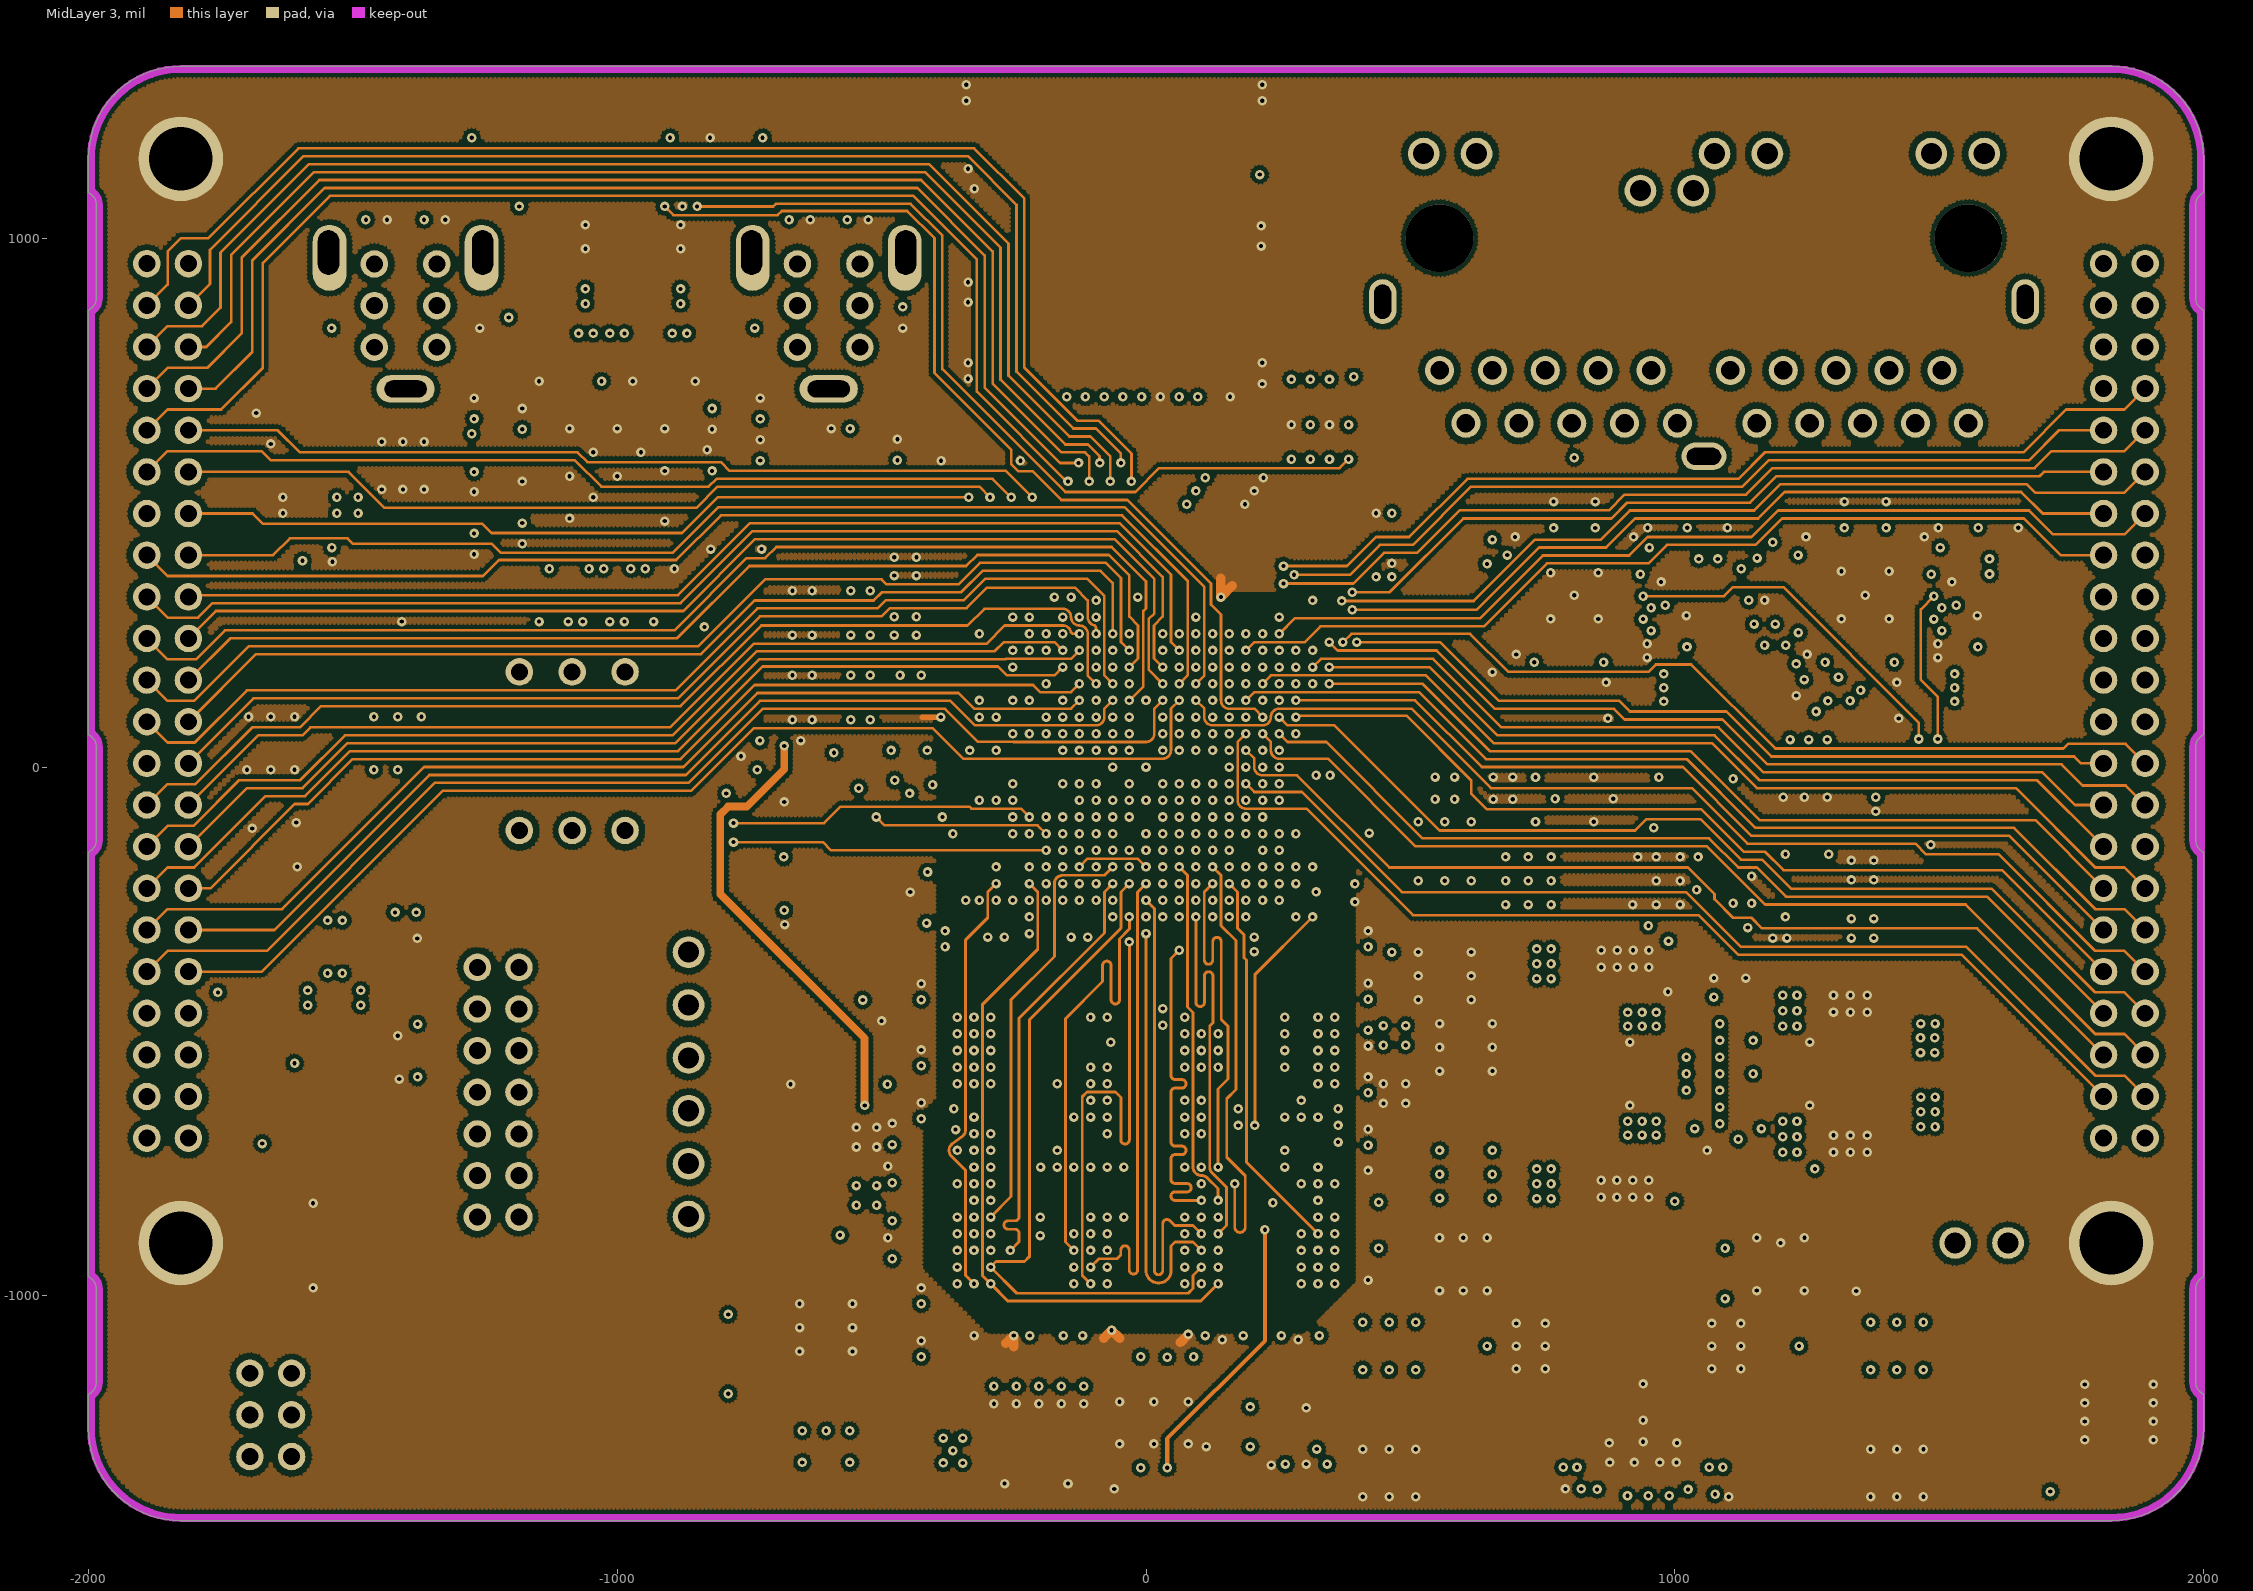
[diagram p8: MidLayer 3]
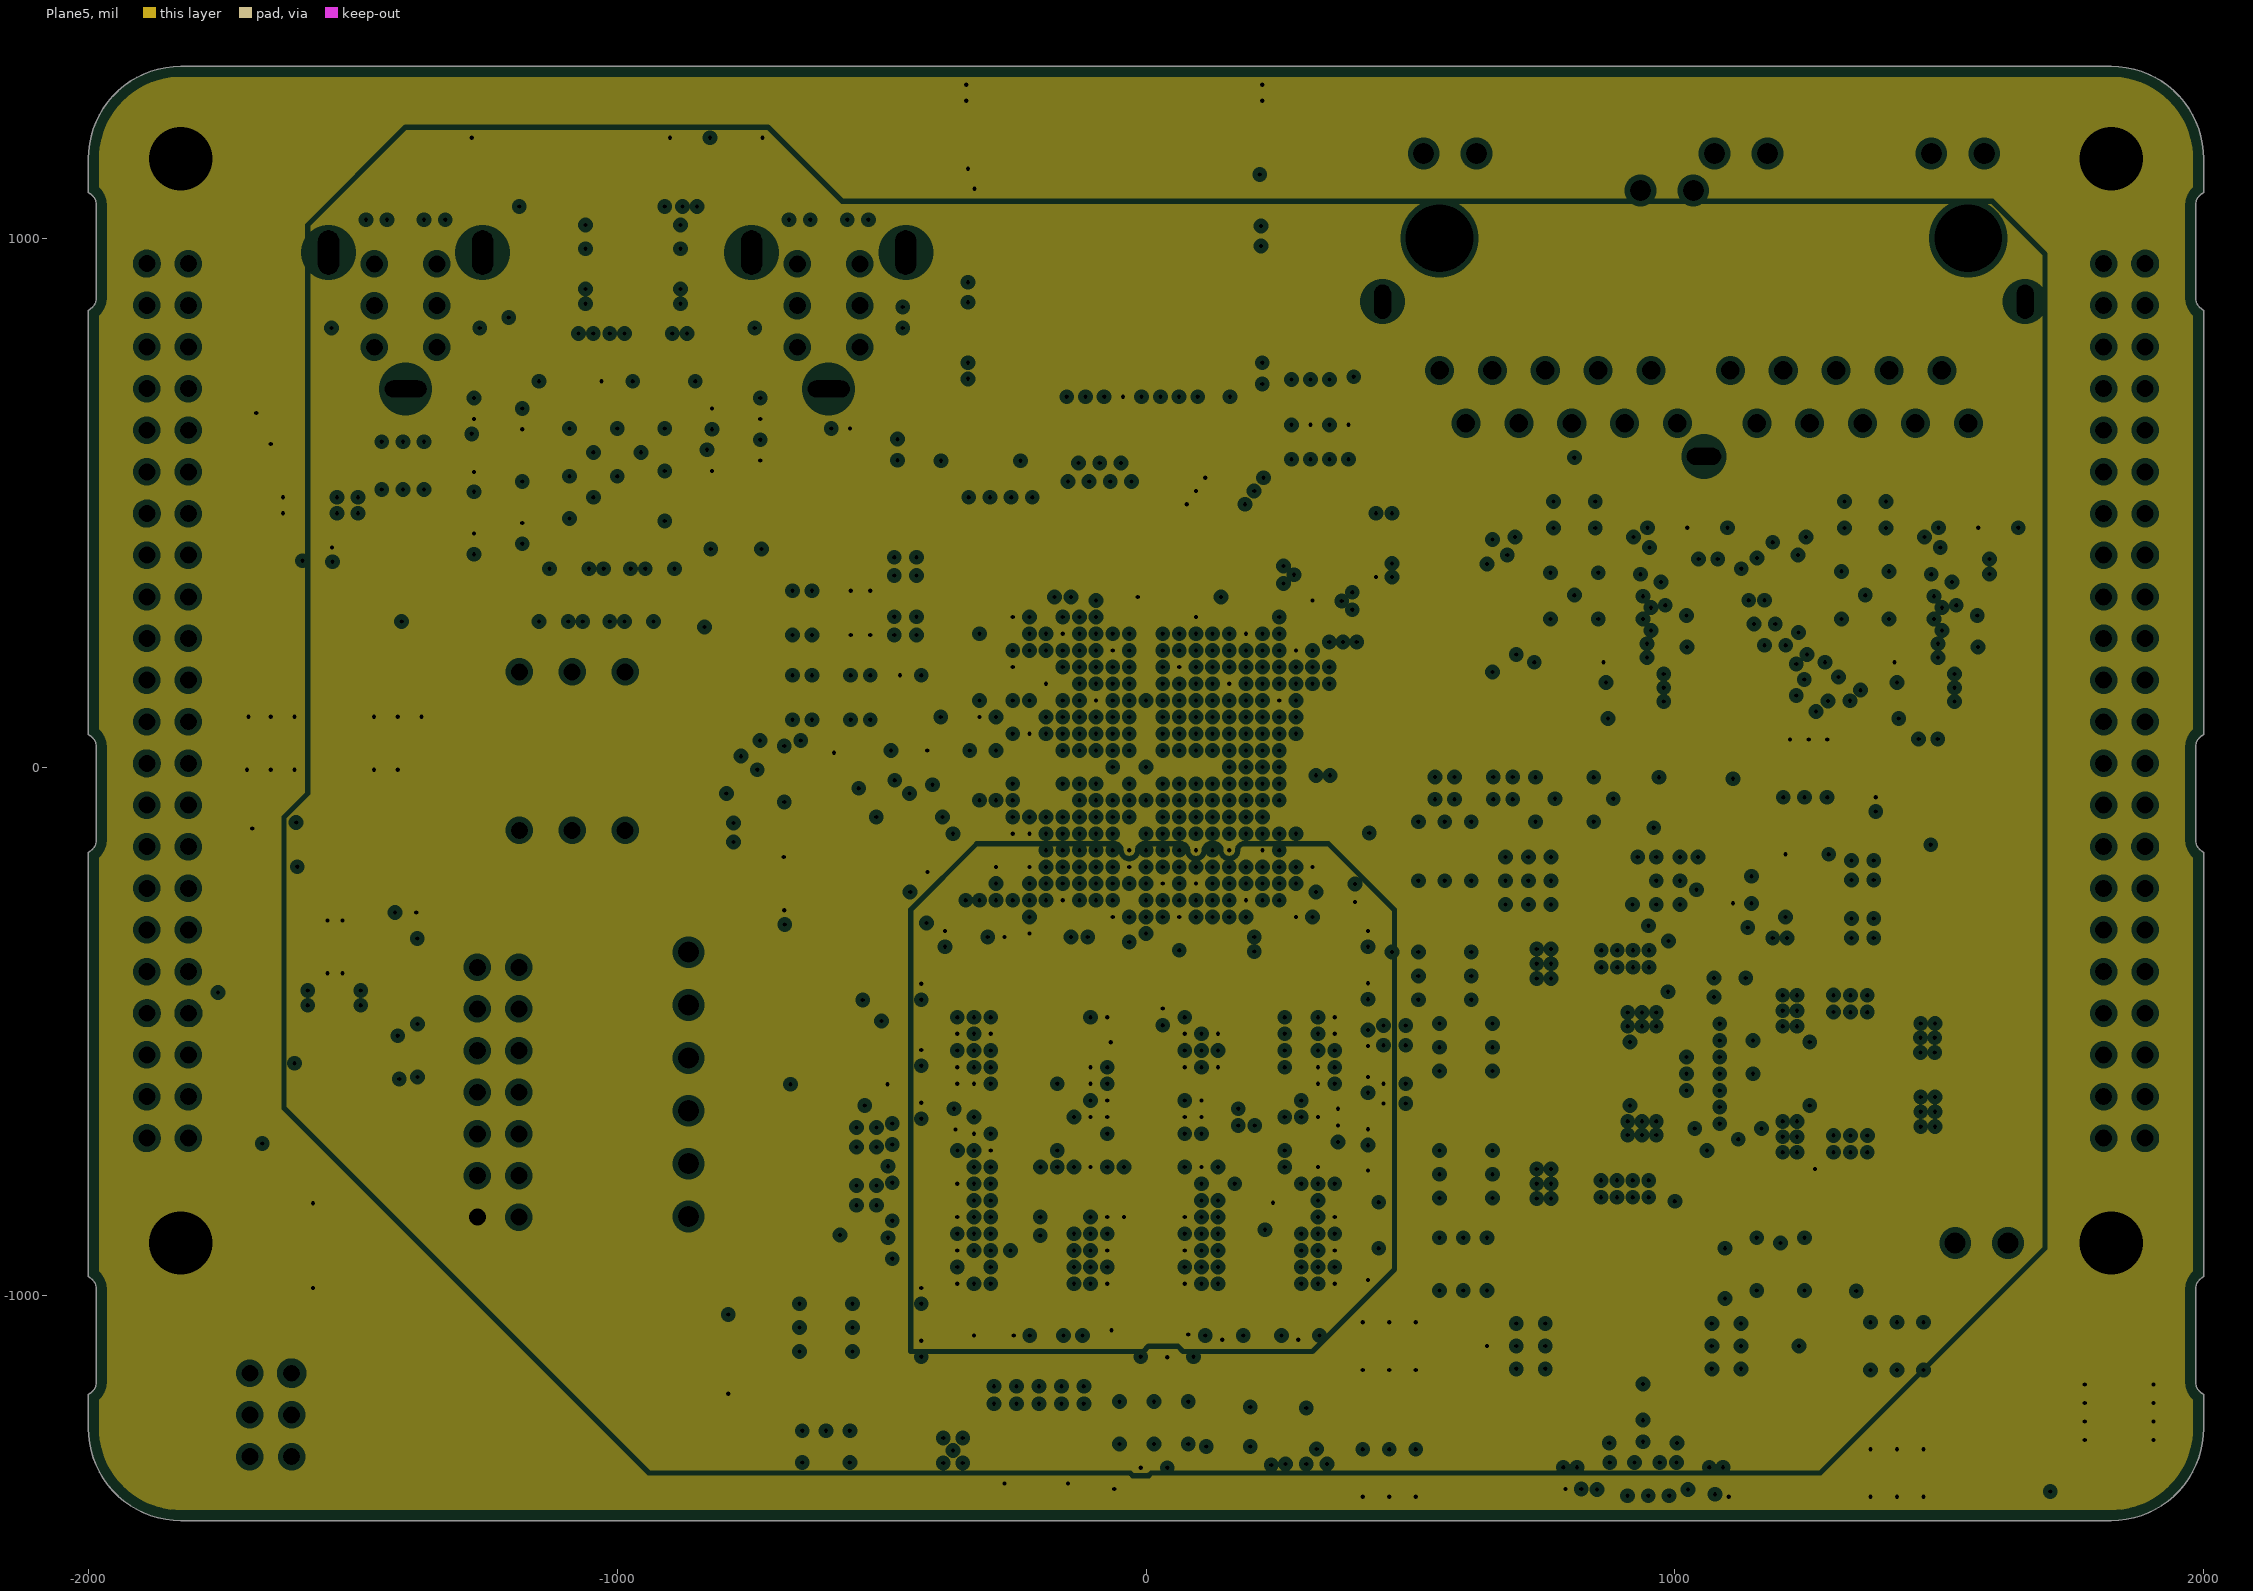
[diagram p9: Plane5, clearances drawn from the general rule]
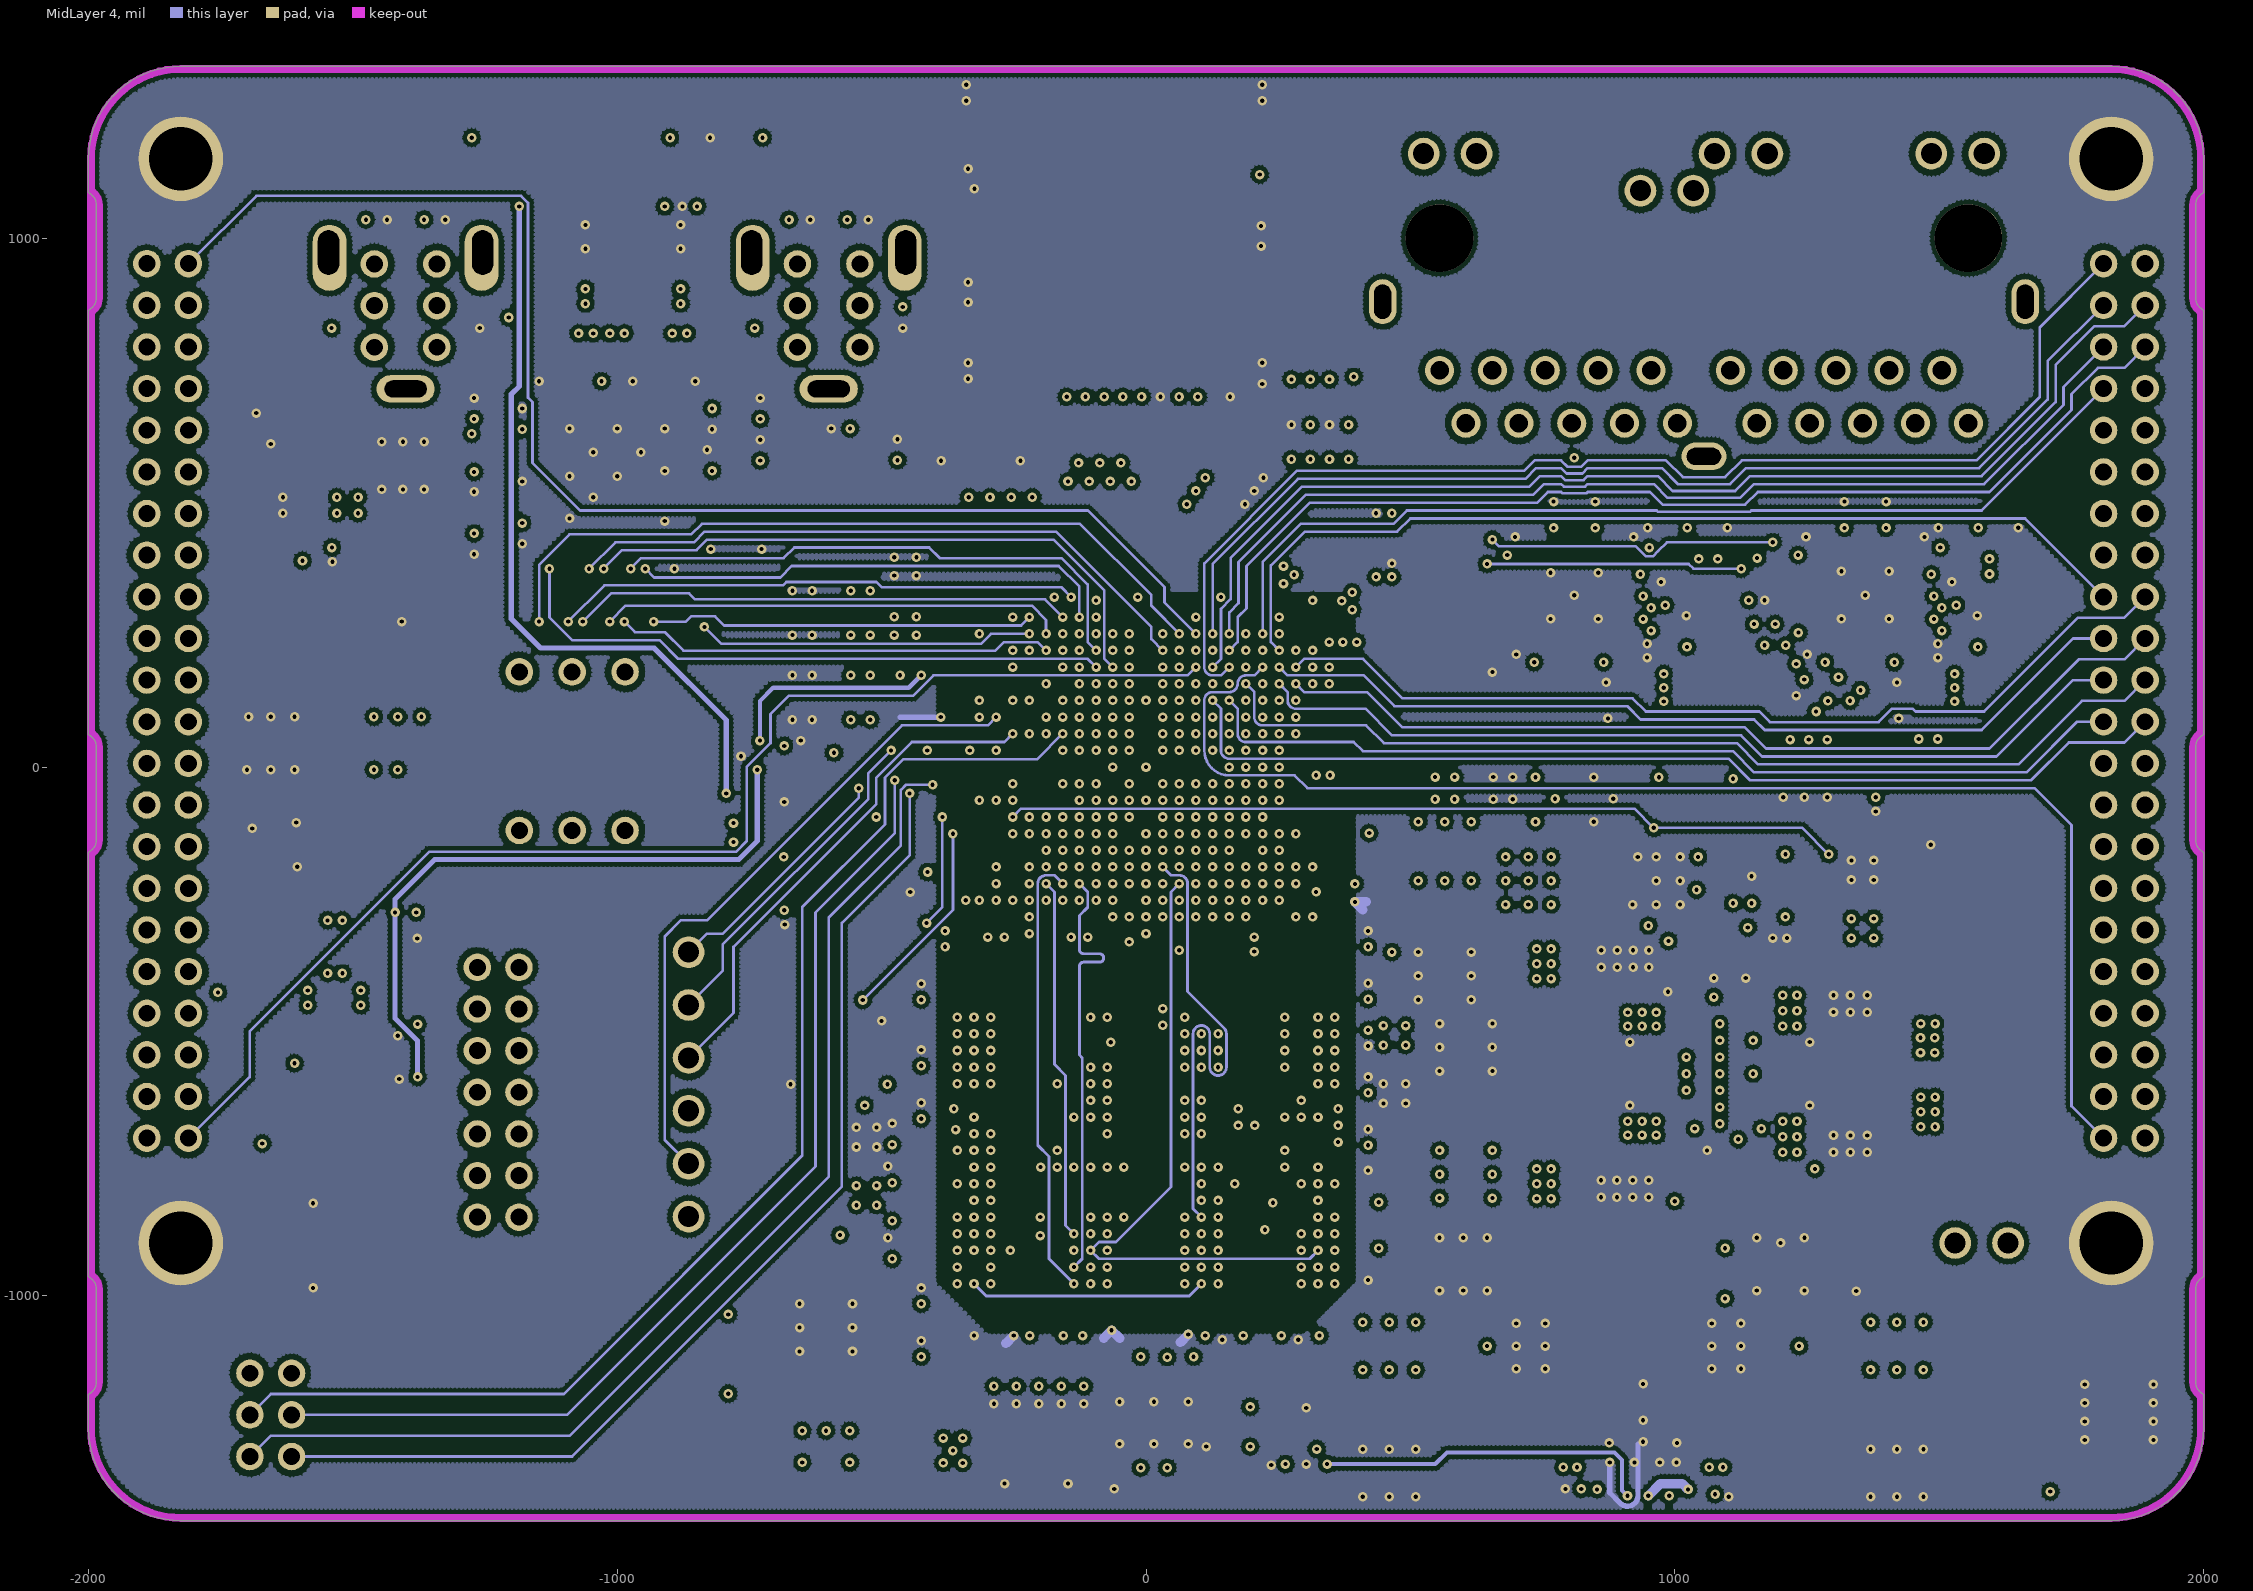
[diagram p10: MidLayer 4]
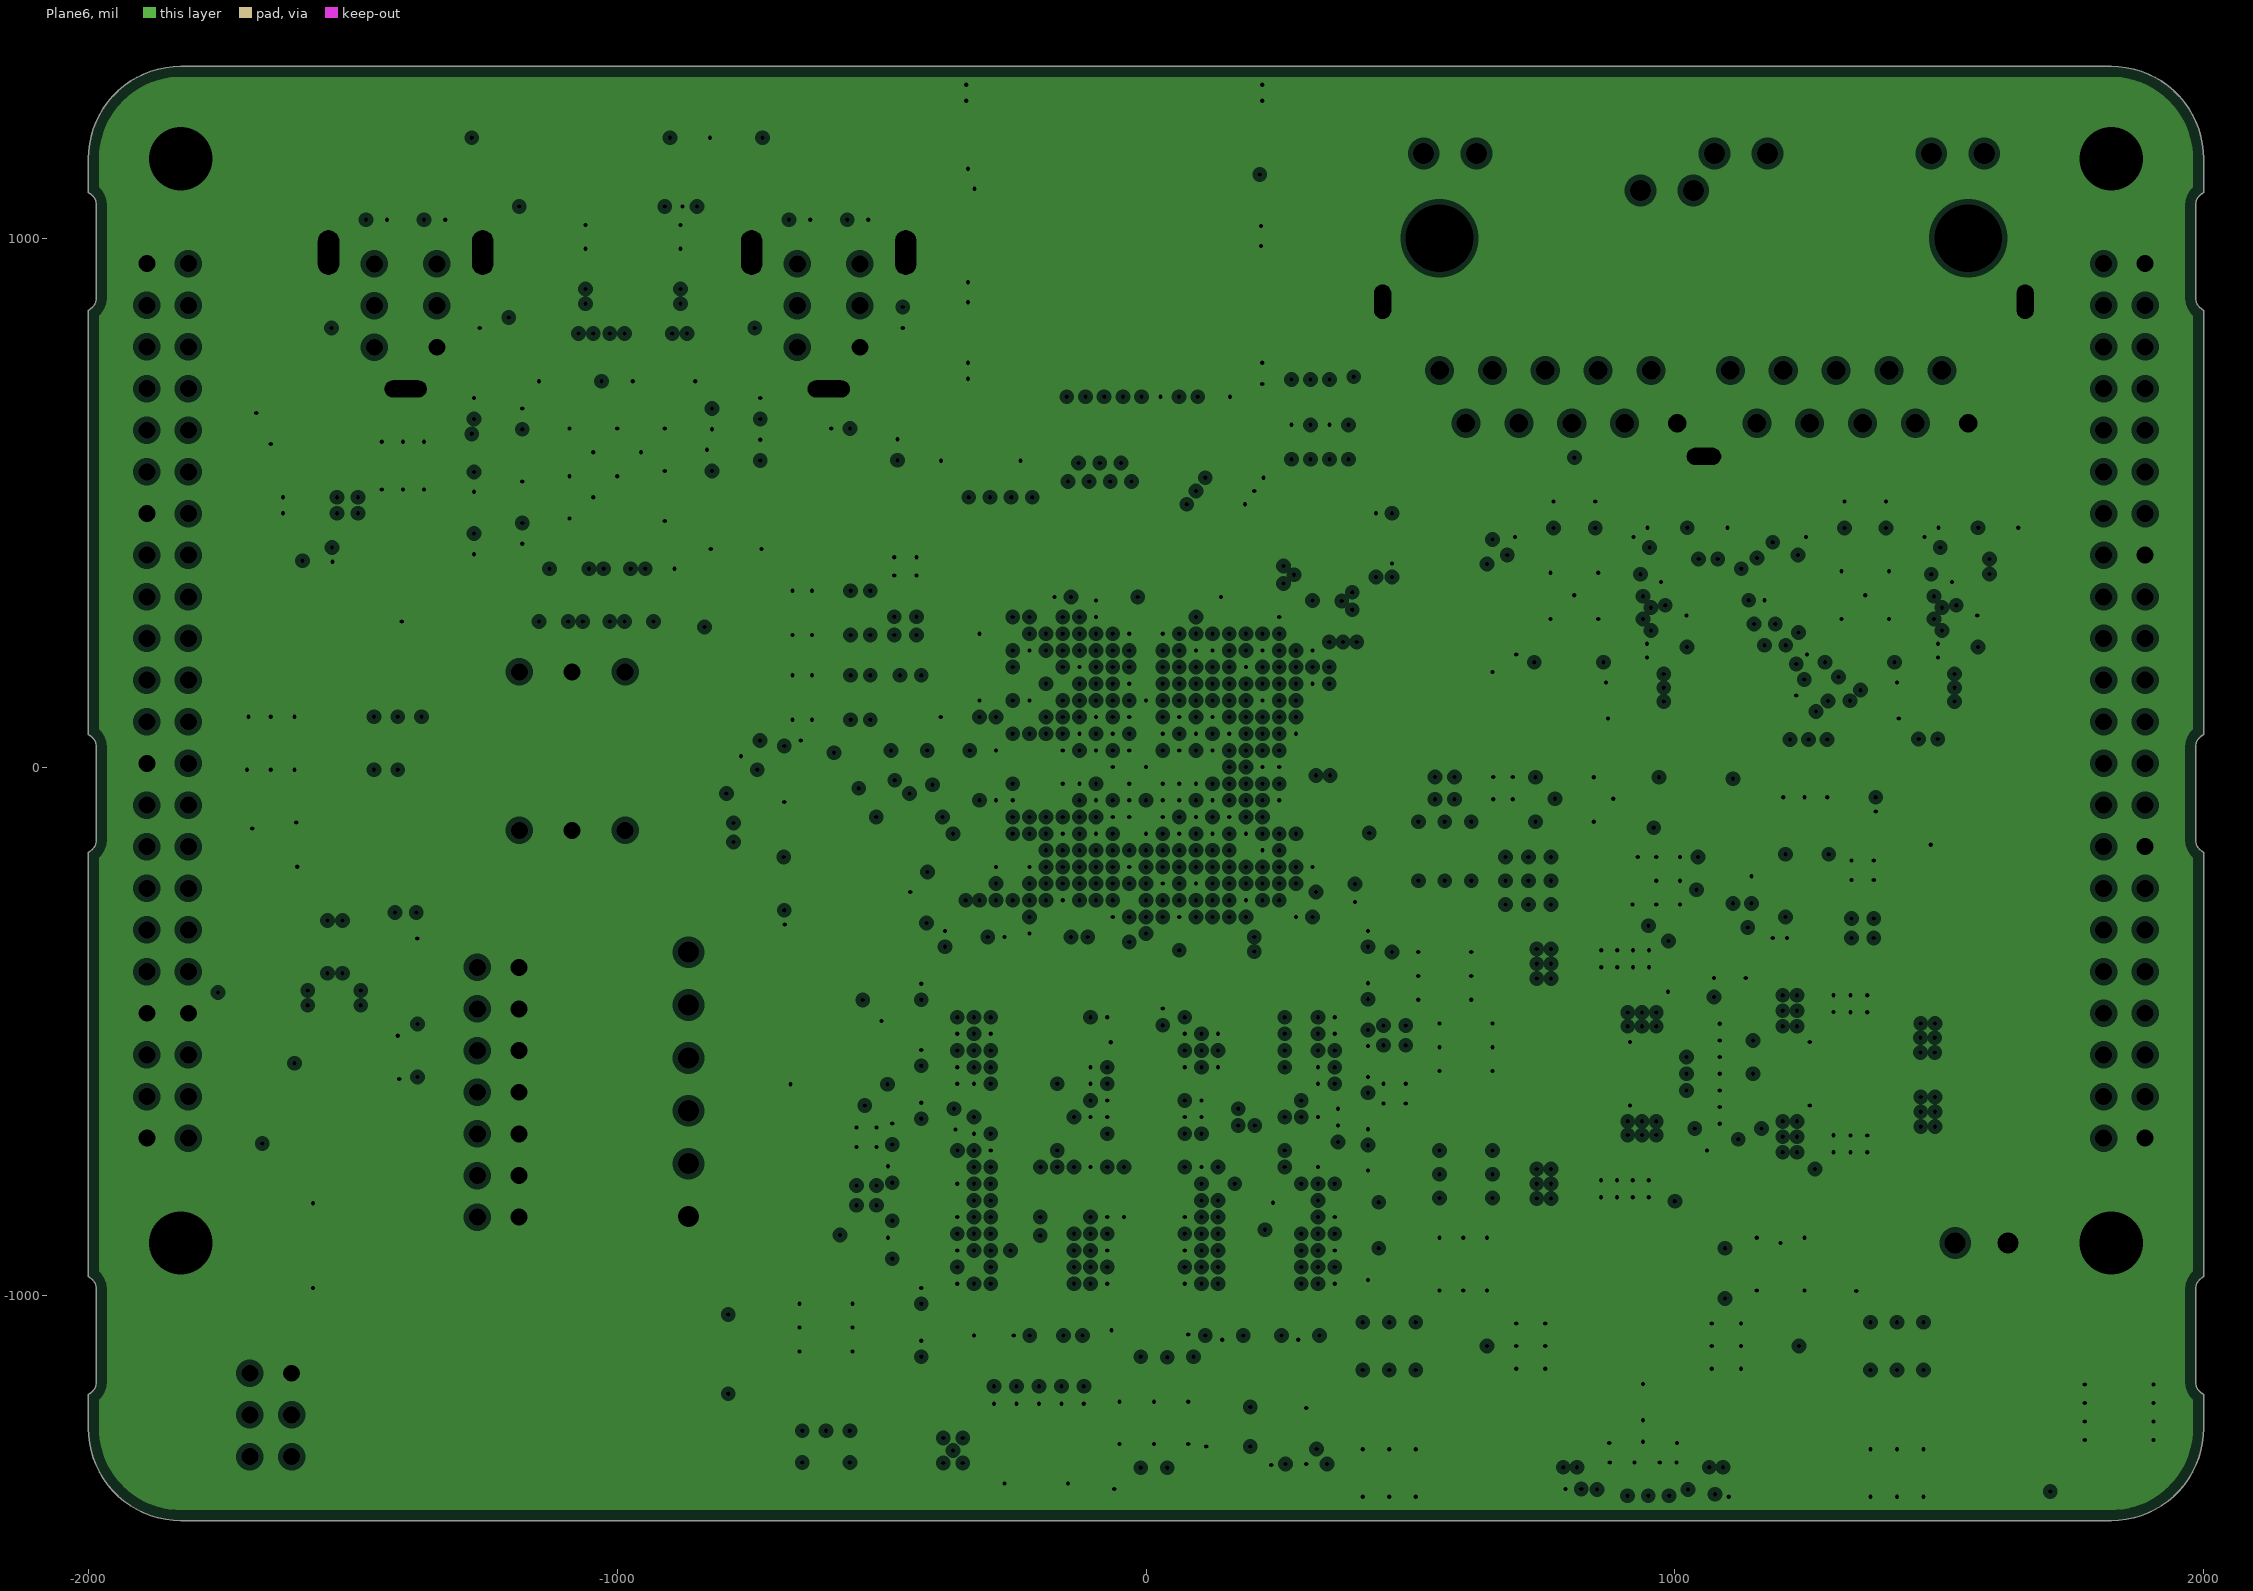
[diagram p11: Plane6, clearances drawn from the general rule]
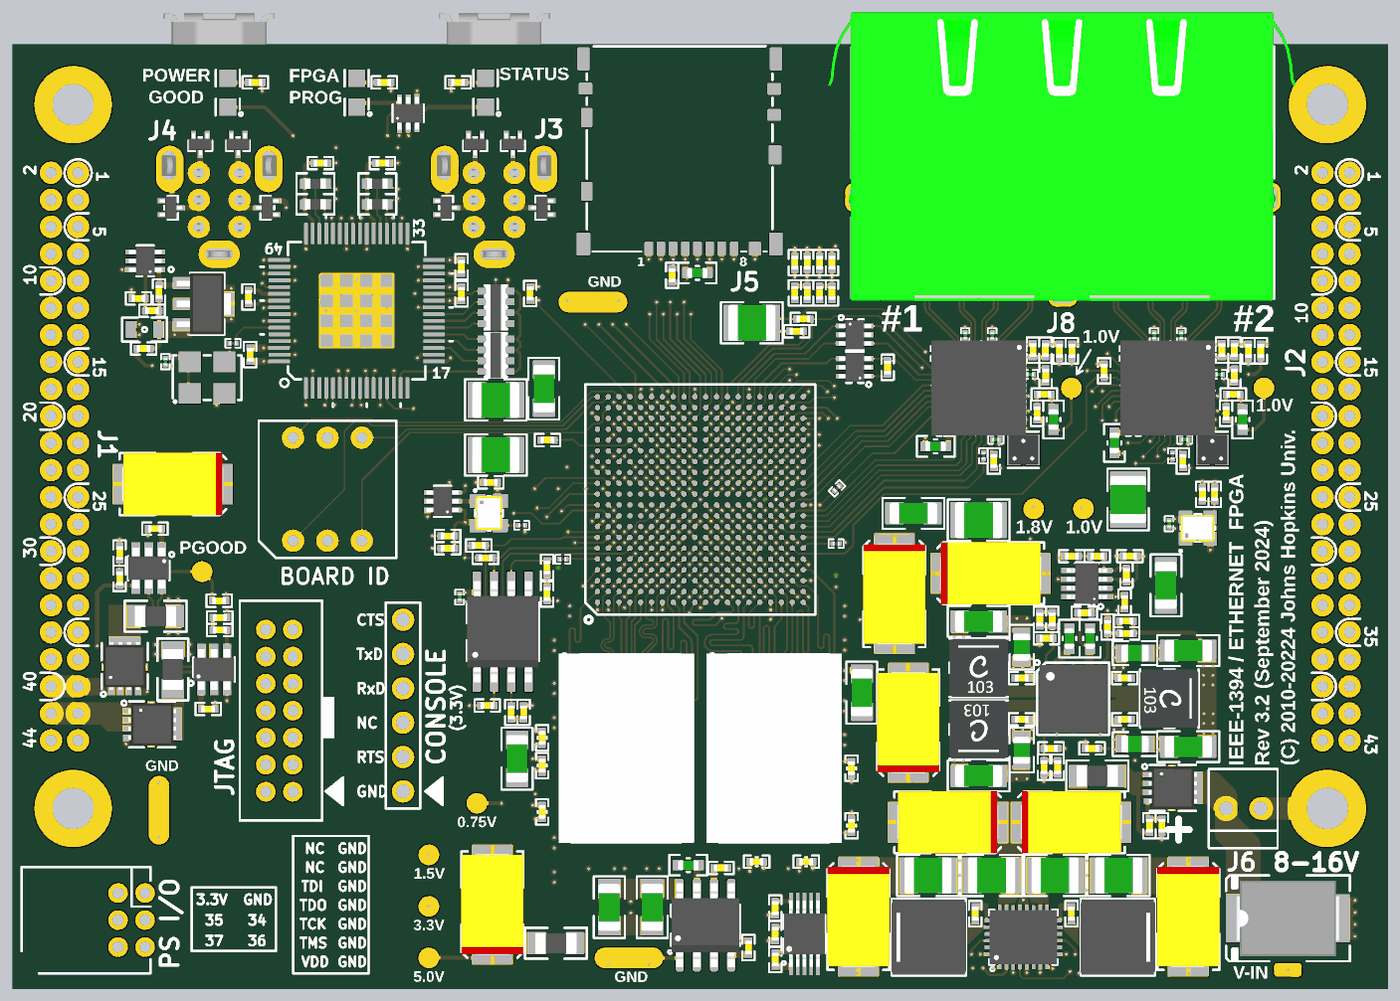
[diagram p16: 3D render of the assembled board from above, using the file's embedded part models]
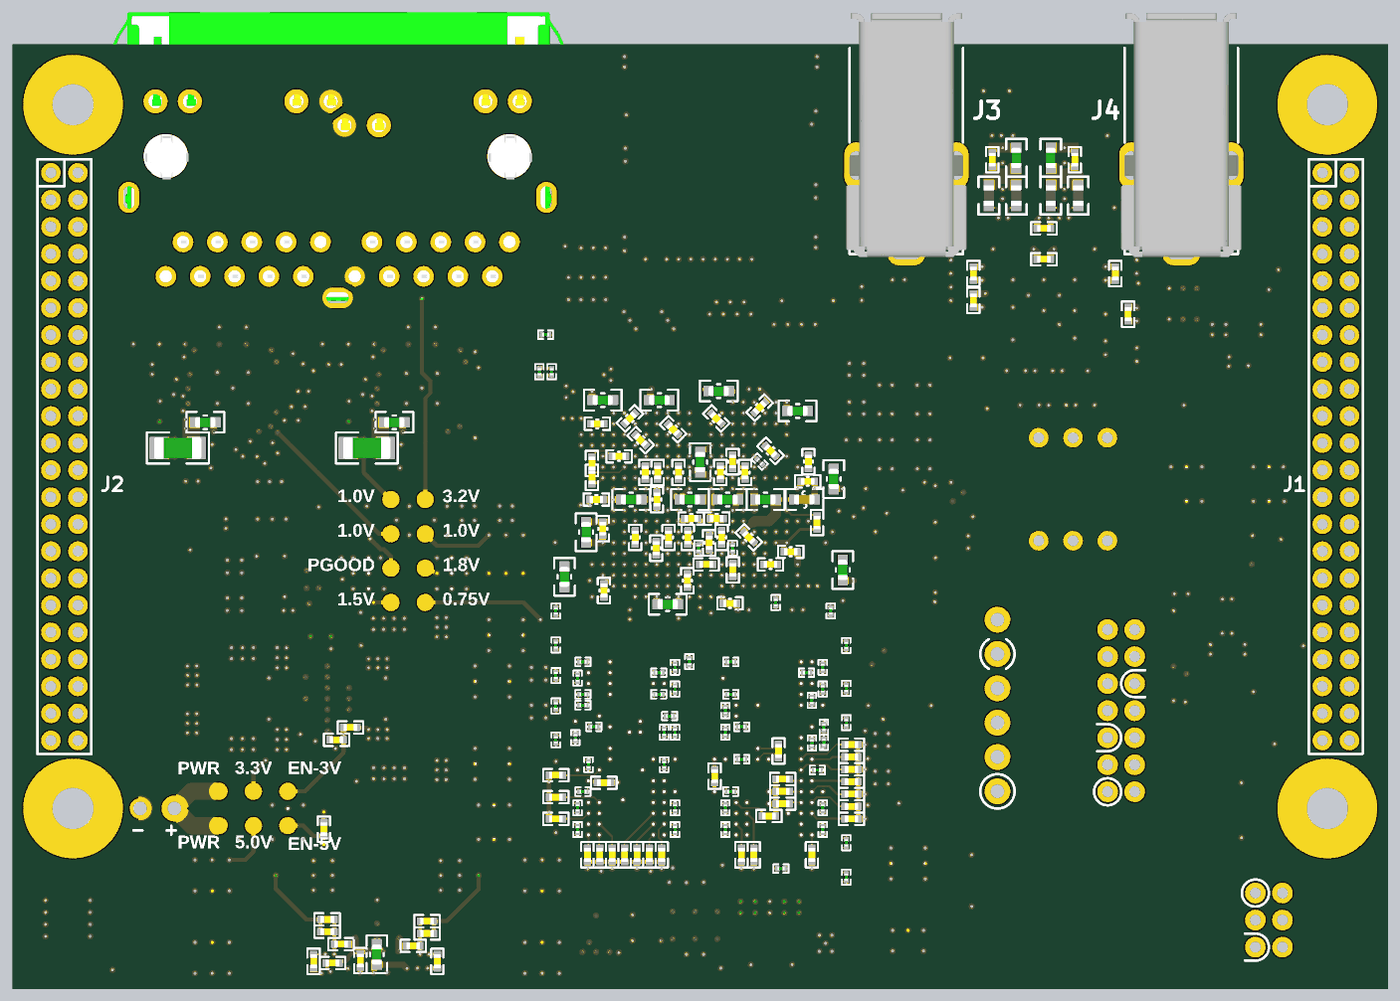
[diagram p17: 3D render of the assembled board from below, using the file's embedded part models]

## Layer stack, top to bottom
Top Solder: solder mask 0.4, Solder Resist, Dk 3.2
Top Layer: signal copper 1.9
Prepreg1: prepreg 2.3, PP-003, Dk 4.3
Plane1: plane copper 0.709, net GND
Core1: core 5, Core-015, Dk 4.4
MidLayer1: signal copper 0.709
Prepreg2: prepreg 4.2, PP-014, Dk 4.2
Plane2: plane copper 0.709, net (Multiple Nets)
Core2: core 5, Core-015, Dk 4.4
MidLayer2: signal copper 0.709
Prepreg3: prepreg 4.2, PP-014, Dk 4.2
Plane3: plane copper 0.709, net (Multiple Nets)
Core3: core 5, Core-015, Dk 4.4
Plane4: plane copper 0.709, net GND
Prepreg4: prepreg 4.2, PP-014, Dk 4.2
MidLayer 3: signal copper 0.709
Core4: core 5, Core-015, Dk 4.4
Plane5: plane copper 0.709, net (Multiple Nets)
Prepreg5: prepreg 4.2, PP-014, Dk 4.2
MidLayer 4: signal copper 0.709
Core5: core 5, Core-015, Dk 4.4
Plane6: plane copper 0.709, net GND
Prepreg6: prepreg 2.3, PP-003, Dk 4.3
Bottom Layer: signal copper 1.9
Bottom Solder: solder mask 0.4, Solder Resist, Dk 3.2

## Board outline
-2000,-1185.91 ccw(c-2010,-1163) -1985,-1163 -1985,-987 ccw(c-2010,-987) -2000,-964.09 -2000,-160.92 ccw(c-2010,-138) -1985,-138 -1985,38 ccw(c-2010,38) -2000,60.91 -2000,864.08 ccw(c-2010,887) -1985,887 -1985,1063 ccw(c-2010,1063) -2000,1085.91 -2000,1150 cw(c-1825,1150) -1825,1325 1825,1325 cw(c1825,1150) 2000,1150 2000,1085.91 ccw(c2010,1063) 1985,1063 1985,887 ccw(c2010,887) 2000,864.09 2000,60.91 ccw(c2010,38) 1985,38 1985,-138 ccw(c2010,-138) 2000,-160.91 2000,-964.08 ccw(c2010,-987) 1985,-987 1985,-1163 ccw(c2010,-1163) 2000,-1185.91 2000,-1250 cw(c1825,-1250) 1825,-1425 -1825,-1425 cw(c-1825,-1250) -2000,-1250

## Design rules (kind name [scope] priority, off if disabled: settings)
Clearance PolyClearKeepout [InPoly vs IsObjectKind(Keepout)] p1 off: gap=20 ignorepadtopadclearanceinfootprint=FALSE
Clearance PolyClear [InPoly] p2: gap=8 ignorepadtopadclearanceinfootprint=FALSE except(12: Arc-THPad Track-THPad SMDPad-THPad THPad-THPad THPad-Via THPad-Fill THPad-Poly THPad-Region THPad-Text THPad-Hole)
Clearance "BGA Breakout" [TouchesRoom('Breakout')] p3: gap=4 ignorepadtopadclearanceinfootprint=FALSE
Clearance [All] p4: gap=5 ignorepadtopadclearanceinfootprint=FALSE
ComponentClearance [All] p1 off: gap=10 collisioncheckmode=3 verticalgap=10 showdistances=FALSE
FabricationTestPointUsage TestPointUsage [All] p1: valid=0 allowmultiple=FALSE
FabricationTestpoint Testpoint [All] p1: side=3 testpointundercomponent=TRUE minsize=40 maxsize=100 preferedsize=60 minholesize=0 maxholesize=40 preferedholesize=32 testpointgrid=1 allowsidetop=TRUE allowsidebottom=TRUE usegrid=TRUE gridtolerance=0.01
Height [All] p1 off: minheight=0 maxheight=1000 prefheight=500
HoleSize [All] p1: absolutevalues=TRUE maxlimit=250 minlimit=8 maxpercent=80.000 minpercent=20.000
HoleToHoleClearance [All] p1 off: gap=10 allowstackedmicrovias=TRUE
LayerPairs [All] p1 off: enforce=TRUE
MinimumSolderMaskSliver [All] p1 off: minsoldermaskwidth=10
NetAntennae [All] p1 off: netantennaetolerance=0
PlaneClearance PlaneClearanceVIA [AsMils(Hole)<10] p1: clearance=8
PlaneClearance PlaneClearance25 [AsMils(Hole)>50] p2: clearance=25
PlaneClearance PlaneClearance12 [AsMils(Hole)>16] p3: clearance=12
PlaneClearance PlaneClearance10 [All] p4: clearance=10
PlaneConnect PlaneDirect [(AsMils(Hole)<15) Or (AsMils(Hole)>100)] p1: planeconnectstyle=Direct reliefexpansion=20 reliefentries=4 reliefconductorwidth=10 reliefairgap=10
PlaneConnect [All] p2: planeconnectstyle=Relief reliefexpansion=12 reliefentries=4 reliefconductorwidth=8 reliefairgap=10
PolygonConnect PolygonConnect_1 [All vs (AsMils(Hole)<12) Or (AsMils(Hole)>70)] p1: connectstyle=Direct reliefconductorwidth=10 reliefentries=4 polygonreliefangle="90 Angle" airgapwidth=10
PolygonConnect [All] p2: thpad.connectstyle=NoConnect thpad.reliefconductorwidth=10 thpad.reliefentries=4 thpad.polygonreliefangle="90 Angle" thpad.airgapwidth=10 smdpad.connectstyle=NoConnect smdpad.reliefconductorwidth=10 smdpad.reliefentries=4 smdpad.polygonreliefangle="90 Angle" smdpad.airgapwidth=10 via.connectstyle=Direct via.reliefconductorwidth=10 via.reliefentries=4 via.polygonreliefangle="90 Angle" via.airgapwidth=10
RoomDefinition Breakout [False] p1: confinementstyle=ConfineIn formatcopy=TRUE lockcomponents=FALSE outline -400,-1125 -400,450 400,450 400,-1125
RoutingVias [All] p1: holewidth=10 width=20 viastyle="Through Hole" minholewidth=8 minwidth=18 maxholewidth=10 maxwidth=20
SilkToSilkClearance [All] p1 off: silktosilkclearance=10
SilkToSolderMaskClearance SilkscreenOverComponentPads [IsPad] p1 off: minsilkscreentomaskgap=10 clearancetoexposedcopper=TRUE
SolderMaskExpansion [All] p1: expansion=4 istentingtop=FALSE
Width WidthENET [InNetClass('DIFF100')] p1: maxlimit=10 minlimit=5.2 preferedwidth=10 toplayer_maxwidth=6 toplayer_prefwidth=6 midlayer1_minwidth=10 midlayer2_minwidth=10 midlayer3_minwidth=10 midlayer4_minwidth=10 bottomlayer_minwidth=10 minimp=50.000000 maximp=50.000000 favimp=50.000000
Width WidthBreakout [TouchesRoom('Breakout')] p2: maxlimit=100 minlimit=4.49 preferedwidth=5
Width [All] p3: maxlimit=250 minlimit=5 preferedwidth=6
17 further rules are at their usual default settings.

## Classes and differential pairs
net class DIFF100: ETH1-A+_5 ETH1-A-_5 ETH1-B+_5 ETH1-B-_5 ETH1-C+_5 ETH1-C-_5 ETH1-D+_5 ETH1-D-_5 ETH2-A+_5 ETH2-A-_5 ETH2-B+_5 ETH2-B-_5 ETH2-C+_5 ETH2-C-_5 ETH2-D+_5 ETH2-D-_5

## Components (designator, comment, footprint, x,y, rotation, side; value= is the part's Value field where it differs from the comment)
C1 "22pF" C0402 988,-349 r270 top
C2 "22pF" C0402 1239.88,-390.15 r180 top
C3 "22pF" C0402 1000,-780 r90 top
C4 "22pF" C0402 1085,-1223 r180 bottom
C5 "22pF" C0402 795,-1228 r0 bottom
C6 "220pF" C0603 -920,995 r90 bottom
C7 "220pF" C0603 -1020,995 r90 bottom
C8 "0.01uF" C0402 -1690,-156 r90 top
C9 "0.01uF" C0402 -1398,-344 r0 top
C10 "0.1uF" C0402 -1315,590 r270 top
C11 "0.1uF" C0402 -1310,422 r270 top
C12 "0.1uF" C0402 -695,678 r90 top
C13 "0.1uF" C0402 -695,599.21 r90 top
C14 "0.1uF" C0402 -610,50 r180 top
C15 "0.1uF" C0402 1235,-299 r270 top
C16 "0.1uF" C0402 935,-520 r180 top
C17 "0.1uF" C0402 935,-640 r180 top
C18 "0.1uF" C0402 1235,-520 r0 top
C19 "0.1uF" C0402 1235,-640 r0 top
C20 "0.1uF" C0402 60,-1073 r0 top
C21 "0.1uF" C0402 140,-1305 r90 top
C22 "0.1uF" C0402 218,-1340 r90 top
C23 "0.1uF" C0402 800,-1206 r270 top
C24 "0.1uF" C0402 1080,-1206 r270 top
C25 "0.1uF" C0402 1058,-700 r0 bottom
C26 "0.1uF" C0402 -795,658.27 r270 bottom
C27 "0.1uF" C0402 -795,580 r90 bottom
C28 "0.1uF" C0402 -1000,700 r0 bottom
C29 "0.1uF" C0402 -1208,658.27 r90 bottom
C30 "0.1uF" C0402 -1245,540 r270 bottom
C31 "1.0uF" C0402 -1105,980 r0 top
C32 "1.0uF" C0402 -925,980 r0 top
C33 "1.0uF" C0402 -1587,-85 r180 top
C34 "1.0uF" C0402 -1432,-610 r0 top
C35 "1.0uF" C0402 968,435 r90 top
C36 "1.0uF" C0402 1001,306 r0 top
C37 "1.0uF" C0402 854,112 r270 top
C38 "1.0uF" C0402 1518,435 r90 top
C39 "1.0uF" C0402 1551,306 r0 top
C40 "1.0uF" C0402 1404,112 r270 top
C41 "22uF" C0805 -1617,495 r180 top
C42 "22uF" C0805 935,-430 r90 top
C43 "22uF" C0805 1265,-447.5 r0 top
C44 "22uF" C0805 935,-730 r270 top
C45 "22uF" C0805 1265,-712.5 r0 top
C46 "220uF" C1206 -455,323 r90 top
C47 "220uF" C1206 -533,-755 r90 top
C48 "220uF" C1206 -265,-1187.5 r270 top
C49 "220uF" C1206 -140,-1187.5 r270 top
C50 "220uF" C1206 620,-40 r0 top
C51 "220uF" C1206 470,-562.5 r270 top
C52 "220uF" C1206 1355,-250 r90 top
C53 "220uF" C1206 810,-355 r0 top
C54 "220uF" C1206 1420,-440 r180 top
C55 "220uF" C1206 810,-805 r0 top
C56 "220uF" C1206 1420,-720 r180 top
C57 "220uF" C1206 1520,150 r180 bottom
C58 "220uF" C1206 970,150 r180 bottom
C59 "10uF" C1210 847.5,-1095 r180 top
C60 "10uF" C1210 1032.5,-1095 r0 top
C61 "100uF" C1210 -595,290 r180 top
C62 "100uF" C1210 150,515 r0 top
C63 "100uF" C1210 1245,0 r270 top
C64 "100uF" C1210 662.5,-1095 r0 top
C65 "100uF" C1210 1217.5,-1095 r180 top
C66 "220uF" C1210 -595,130 r180 top
C67 "220uF" C1210 810,-60 r0 top
C68 "33uF" CAP-D-31 720,-940 r180 top
C69 "33uF" CAP-D-31 1080,-940 r0 top
C70 "330uF" CAP-D-31 -605,-1180 r90 top
C71 "330uF" CAP-D-31 1420,-1215 r270 top
C72 "470uF" CAP-D-31 -1535,45 r180 top
C73 "470uF" CAP-D-31 460,-1215 r270 top
C74 "680uF" CAP-D-43 845,-215 r0 top
C75 "1000uF" CAP-D-43 565,-275 r270 top
C76 "1000uF" CAP-D-43 605,-650 r90 top
C77 "4700pF" C0402 765,-1345 r270 bottom
C78 "4700pF" C0402 1125,-1345 r270 bottom
CB1 "0.1uF" C0201 -235,-1075 r180 bottom
CB2 "0.1uF" C0201 4.75,-141.5 r90 bottom
CB3 "0.1uF" C0201 420,-424 r90 bottom
CB4 "0.1uF" C0201 420,-700 r90 bottom
CB5 "0.1uF" C0201 420,-325 r90 bottom
CB6 "0.1uF" C0201 -425,-425 r90 bottom
CB7 "0.1uF" C0201 -380,-325 r90 bottom
CB8 "0.1uF" C0201 -425,-1100 r90 bottom
CB9 "0.1uF" C0201 420,-512.5 r270 bottom
CB10 "0.1uF" C0201 -425,-1000 r90 bottom
CB11 "0.1uF" C0201 -425,-550 r90 bottom
CB12 "0.1uF" C0201 -425,-650 r90 bottom
CB13 "0.1uF" C0201 340.98,-473.03 r0 bottom
CB14 "0.1uF" C0201 325.24,-772.24 r90 bottom
CB15 "0.1uF" C0201 73.27,-488.78 r270 bottom
CB16 "0.1uF" C0201 -73.27,-614.76 r270 bottom
CB17 "0.1uF" C0201 73.27,-551.77 r270 bottom
CB18 "0.1uF" C0201 104.76,-772.24 r90 bottom
CB19 "0.1uF" C0201 -356.73,-551.77 r270 bottom
CB20 "0.1uF" C0201 -340.98,-787.99 r180 bottom
CB21 "0.1uF" C0201 -356.73,-961.22 r270 bottom
CB22 "0.1uF" C0201 -356.73,-898.23 r270 bottom
CB23 "0.1uF" C0201 -89.02,-567.52 r180 bottom
CB24 "0.1uF" C0201 -325.24,-709.25 r90 bottom
CB25 "0.1uF" C0201 340.98,-599.02 r180 bottom
CB26 "0.1uF" C0201 89.02,-630.51 r0 bottom
CB27 "0.1uF" C0201 120.51,-504.53 r0 bottom
CB28 "0.1uF" C0201 -356.73,-488.78 r270 bottom
CB29 "0.1uF" C0201 -89.02,-473.03 r0 bottom
CB30 "0.1uF" C0201 -220,-300 r270 bottom
CB31 "0.1uF" C0201 104.76,-677.76 r90 bottom
CB32 "0.1uF" C0201 120.51,-567.52 r0 bottom
CB33 "0.1uF" C0201 -73.27,-898.23 r270 bottom
CB34 "0.1uF" C0201 356.73,-961.22 r270 bottom
CB35 "0.1uF" C0201 -120.51,-756.5 r0 bottom
CB36 "0.1uF" C0201 -325,-585 r270 bottom
CB37 "0.1uF" C0201 -73.27,-677.76 r90 bottom
CB38 "0.1uF" C0201 73.27,-898.23 r270 bottom
CB39 "0.1uF" C0201 356.73,-520.28 r90 bottom
CB40 "0.1uF" C0201 -360,-663.5 r270 bottom
CB41 "0.1uF" C0201 340.98,-567.52 r180 bottom
CB42 "0.1uF" C0201 309.49,-662.01 r0 bottom
CB43 "0.1uF" C0201 363.27,-693.5 r90 bottom
CB44 "0.1uF" C0201 356.73,-898.23 r270 bottom
CB45 "0.1uF" C0201 73.27,-961.22 r270 bottom
CB46 "0.1uF" C0201 -73.27,-961.22 r270 bottom
CB47 "0.1uF" C0201 -309.49,-504.53 r0 bottom
CB48 "0.1uF" C0201 -120.51,-662.01 r0 bottom
CB49 "0.1uF" C0201 860,175 r0 top
CB50 "0.1uF" C0201 1410,175 r0 top
CB51 "0.1uF" C0201 710,198 r180 top
CB52 "0.1uF" C0201 1260,198 r180 top
CB53 "0.1uF" C0201 960,364.37 r0 top
CB54 "0.1uF" C0201 1510,364.37 r0 top
CB55 "0.1uF" C0201 937,425 r90 top
CB56 "0.1uF" C0201 1233,425 r90 top
CB57 "0.1uF" C0201 770.67,477 r90 top
CB58 "0.1uF" C0201 1320.63,477 r90 top
CB59 "0.1uF" C0201 683,425 r90 top
CB60 "0.1uF" C0201 1487,425 r90 top
CB61 "0.1uF" C0201 849.41,477 r90 top
CB62 "0.1uF" C0201 1399.37,477 r90 top
CB63 "0.1uF" C0201 340.98,-850.98 r0 bottom
CB64 "0.1uF" C0201 31.5,-472.44 r90 bottom
CB65 "0.1uF" C0201 73.27,-677.76 r90 bottom
CB66 "0.1uF" C0201 420,-601 r90 bottom
CB67 "0.1uF" C0201 -94.49,-141.73 r90 bottom
CB68 "0.1uF" C0201 -89.02,-850.99 r0 bottom
CB69 "0.1uF" C0201 -360,-707.5 r90 bottom
CB70 "0.1uF" C0201 468,372.2 r90 bottom
CB71 "0.1uF" C0201 450,480 r180 bottom
CB72 "0.1uF" C0201 432,372.2 r90 bottom
CB73 "0.1uF" C0201 1364,-70.5 r270 top
CB74 "0.1uF" C0201 -1556.5,401.5 r270 top
CB75 "0.1uF" C0201 -700.5,-284.5 r270 top
CB76 "0.47uF" CB0402 62.99,78.74 r90 bottom
CB77 "0.47uF" CB0402 128,-141.73 r90 bottom
CB78 "0.47uF" CB0402 -130.48,78.74 r270 bottom
CB79 "0.47uF" CB0402 123.75,78.74 r90 bottom
CB80 "0.47uF" CB0402 26,-55.12 r0 bottom
CB81 "0.47uF" CB0402 -62.49,-110.24 r90 bottom
CB82 "0.47uF" CB0402 36,-110.24 r90 bottom
CB83 "0.47uF" CB0402 125.98,0 r90 bottom
CB84 "0.47uF" CB0402 92,-110.24 r90 bottom
CB85 "0.47uF" CB0402 -58.49,78.74 r270 bottom
CB86 "0.47uF" CB0402 159.75,78.74 r270 bottom
CB87 "0.47uF" CB0402 -204.72,-188.98 r180 bottom
CB88 "0.47uF" CB0402 -204.72,141.73 r225 bottom
CB89 "0.47uF" CB0402 -314.96,110.24 r90 bottom
CB90 "0.47uF" CB0402 -263.5,-152 r180 bottom
CB91 "0.47uF" CB0402 -47.24,236.22 r45 bottom
CB92 "0.47uF" CB0402 299.21,220.47 r0 bottom
CB93 "0.47uF" CB0402 283.46,-85 r90 bottom
CB94 "0.47uF" CB0402 -26,-125.98 r90 bottom
CB95 "0.47uF" CB0402 280,-265 r270 bottom
CB96 "0.47uF" CB0402 -94.49,110.24 r270 bottom
CB97 "0.47uF" CB0402 236.22,125.98 r180 bottom
CB98 "0.47uF" CB0402 302,0 r180 bottom
CB99 "0.47uF" CB0402 -86.61,-302.5 r0 bottom
CB100 "0.47uF" CB0402 -173.23,267.72 r135 bottom
CB101 "0.47uF" CB0402 204.72,236.22 r315 bottom
CB102 "0.47uF" CB0402 -313,53 r0 bottom
CB103 "0.47uF" CB0402 37.5,-236.22 r90 bottom
CB104 "0.47uF" CB0402 78.74,204.72 r45 bottom
CB105 "0.47uF" CB0402 173.23,173.23 r45 bottom
CB106 "0.47uF" CB0402 188.98,-110.24 r270 bottom
CB107 "0.47uF" CB0402 -48,-55.24 r0 bottom
CB108 "0.47uF" CB0402 -141.73,-110.24 r225 bottom
CB109 "0.47uF" CB0402 -460,-775 r90 top
CB110 "0.47uF" CB0402 -460,-694 r90 top
CB111 "0.47uF" CB0402 -460,-910 r90 top
CB112 "0.47uF" CB0402 440,-950.04 r270 top
CB113 "0.47uF" CB0402 440,-782.91 r90 top
CB114 "0.47uF" CB0402 308,-1055 r180 top
CB115 "0.47uF" CB0402 164,-1055 r180 top
CB116 "10uF" CB0603 -388.5,60 r90 bottom
CB117 "10uF" CB0603 -190,0 r0 bottom
CB118 "10uF" CB0603 30,0 r180 bottom
CB119 "10uF" CB0603 0,109 r90 bottom
CB120 "10uF" CB0603 200.79,0 r0 bottom
CB121 "10uF" CB0603 -80,0 r0 bottom
CB122 "10uF" CB0603 94.49,-305 r180 bottom
CB123 "10uF" CB0603 283.46,289.5 r180 bottom
CB124 "10uF" CB0603 119,289.5 r0 bottom
CB125 "10uF" CB0603 -283.46,258 r180 bottom
CB126 "10uF" CB0603 -54,316 r180 bottom
CB127 "10uF" CB0603 332,-95 r90 bottom
CB128 "10uF" CB0603 395,-225 r270 bottom
CB129 "10uF" CB0603 -415,-205 r270 bottom
CB130 "10uF" CB0603 890,225 r0 bottom
CB131 "10uF" CB0603 1440,225 r0 bottom
CB132 "10uF" CB0603 -8.5,660 r0 top
CB133 "10uF" CB0603 -35,-1065 r180 top
CB134 "10uF" CB0603 1578,233 r90 top
CB135 "10uF" CB0603 1028,233 r90 top
CB136 "10uF" CB0603 1205,165 r270 top
CB137 "10uF" CB0603 1074,-405 r90 top
CB138 "10uF" CB0603 941,-1325 r90 bottom
CB139 "10uF" CB0603 1134,-405 r90 top
CB140 "10uF" CB0603 685,155 r180 top
D1 "SMCJ16" DIODE-SMC 1710,-1220 r0 top
D2 "LED" LED-0805 -1375,1185 r90 top
D3 "LED" LED-0805 -625,1185 r90 top
D4 "LED" LED-0805 -1000,1185 r90 top
D5 "BAV99T" SOT-523 -1345,1035 r180 top
D6 "BAV99T" SOT-523 -1455,1035 r180 top
D7 "BAV99T" SOT-523 -1260,850 r90 top
D8 "BAV99T" SOT-523 -1540,850 r270 top
D9 "BAV99T" SOT-523 -545,1035 r180 top
D10 "BAV99T" SOT-523 -655,1035 r180 top
D11 "BAV99T" SOT-523 -460,850 r90 top
D12 "BAV99T" SOT-523 -740,850 r270 top
J1 "HEADER 22x2-1" HDR-22x2-2MM -1850,125 r270 top locked
J2 "HEADER 22x2-1" HDR-22x2-2MM 1850,125 r270 top locked
J3 "Firewire6" FIREWIRE6-RA -600,715 r180 bottom locked
J4 "Firewire6" FIREWIRE6-RA -1400,715 r180 bottom locked
J5 "MicroSDCARD" CONN-uSD-JAE-ST12S0 -60,1325 r180 top
J6 "HEADER 2" HDR-2x1-100 1580,-900 r0 top
J7 "HEADER 7X2-1" HDR-7x2-2MM -1225,-615 r90 top
J8 "RJ-45-2-TRANSFORMER-PULSE" CONN-RJ-45-DUAL-PULSE-JXD0-2015NL 1055,1000 r180 top locked
J9 "HEADER 3X2-1" HDR-3x2-2MM -1655,-1225 r270 top locked
J10 "HEADER 6" HDR-6x1-100 -865,-600 r90 top
L1 "1.5uH" INDUCTOR-XGL5030 1215,-1275 r270 top
L2 "1.2uH" INDUCTOR-XGL5030 665,-1275 r90 top
L3 "0.68uH" INDUCTOR-XAL4040 1365,-580 r270 top
L4 "1.5uH" INDUCTOR-XAL4040 810,-670 r180 top
L5 "1.5uH" INDUCTOR-XAL4040 810,-490 r0 top
L6 "3.3uH" INDUCTOR-EPL2014 940,145 r0 top
L7 "3.3uH" INDUCTOR-EPL2014 1490,145 r0 top
L8 "FERRITE" L0603 -303.15,0 r0 bottom
L11 "FERRITE" L0402 980,251 r90 top
L12 "FERRITE" L0402 1530,251 r90 top
L13 "FERRITE" L0402 1004,435 r90 top
L14 "FERRITE" L0402 1554,435 r90 top
L15 "FERRITE" R1206#1 1155,-805 r180 top
L16 "FERRITE" R1206#2 -420,-1292.5 r180 top
M1 "MHOLE" MHOLE4 -1825,1150 r270 top
M2 "MHOLE" MHOLE4 1825,1150 r270 top
M3 "MHOLE" MHOLE4 -1825,-900 r270 top locked
M4 "MHOLE" MHOLE4 1825,-900 r270 top
Q1 "Si7108" POWERPAK-1212#1 -1595,-655 r270 top
Q2 "Si7108" POWERPAK-1212#2 -1675,-485 r0 top
Q3 "Si7611" POWERPAK-1212#2 1375,-840 r270 top
Q4 "PMG370" SC70-6-NP -850,1125 r0 top
Q5 "PMG370" SC70-6-NP -750,-5 r90 top
Q6 "DCX69-16" SOT-89 -1445,570 r270 top
R1 "49.9" R0201 397.5,32.5 r45 top
R2 "49.9" R0201 395,-128.48 r0 top
R3 "49.9" R0201 824,127 r90 top
R4 "49.9" R0201 1374,127 r90 top
R5 "49.9" R0201 -520,-75 r180 top
R6 "49.9" R0201 -400,-174 r180 top
R7 "49.9" R0201 -1360,455 r0 top
R8 "49.9" R0201 -173.23,110.24 r45 bottom
R9 "4.99" R0402 1118,-330 r0 top
R10 "40.2" R0402 420,-803 r0 bottom
R11 "40.2" R0402 420,-867 r0 bottom
R12 "40.2" R0402 420,-930 r0 bottom
R13 "40.2" R0402 328,-1035 r270 bottom
R14 "40.2" R0402 292,-1035 r270 bottom
R15 "40.2" R0402 256,-1035 r270 bottom
R16 "40.2" R0402 220,-1035 r270 bottom
R17 "40.2" R0402 184,-1035 r270 bottom
R18 "40.2" R0402 148,-1035 r270 bottom
R19 "40.2" R0402 112,-1035 r270 bottom
R20 "40.2" R0402 -120,-1035 r270 bottom
R21 "40.2" R0402 -156,-1035 r270 bottom
R22 "40.2" R0402 -240,-814 r0 bottom
R23 "40.2" R0402 -240,-850 r0 bottom
R24 "40.2" R0402 -240,-886 r0 bottom
R25 "40.2" R0402 -200,-922 r180 bottom
R26 "40.2" R0402 -440,-714 r180 bottom
R27 "40.2" R0402 -440,-750 r180 bottom
R28 "40.2" R0402 -440,-786 r180 bottom
R29 "40.2" R0402 -440,-822 r180 bottom
R30 "40.2" R0402 -440,-858 r180 bottom
R31 "40.2" R0402 -440,-894 r180 bottom
R32 "40.2" R0402 -440,-930 r180 bottom
R33 "80.6" R0402 -17.5,-188.98 r180 bottom
R34 "80.6" R0402 -95,-205 r90 bottom
R35 "80.6" R0402 -228,-732.5 r90 bottom
R36 "100" R0402 -1690,-230 r90 top
R37 "100" R0402 -1398,-380 r180 top
R38 "100" R0402 1461,15 r90 top
R39 "100" R0402 1497,15 r90 top
R40 "240" R0402 275,690 r270 top
R41 "240" R0402 311,690 r90 top
R42 "240" R0402 347,690 r270 top
R43 "240" R0402 383,690 r90 top
R44 "240" R0402 280,-825 r180 bottom
R45 "240" R0402 -42,-806 r270 bottom
R46 "499" R0402 -1295,1215 r0 top
R47 "499" R0402 -920,1215 r180 top
R48 "499" R0402 -705,1215 r180 top
R49 "499" R0402 275,602 r270 top
R50 "499" R0402 311,602 r270 top
R51 "499" R0402 347,602 r270 top
R52 "499" R0402 383,602 r270 top
R53 "499" R0402 -445,173.5 r180 top
R54 "499" R0402 -514,-620 r90 top
R55 "499" R0402 -340,-67 r270 bottom
R56 "1.00K" R0402 -1575,605 r90 top
R57 "1.00K" R0402 -1620,440 r0 top
R58 "1.00K" R0402 300,526 r180 top
R59 "1.00K" R0402 280,490 r180 top
R60 "1.00K" R0402 315,105 r90 bottom
R60A "OPEN" R0402 315,65 r270 bottom
R61 "1.50K" R0402 -1400,-295 r180 top
R62 "1.50K" R0402 545,385 r270 top
R63 "1.50K" R0402 1175,375 r90 top
R64 "1.50K" R0402 1250,-165 r0 top
R65 "2.49K" R0402 1005,361 r270 top
R66 "2.49K" R0402 1554,361 r270 top
R67 "4.99K" R0402 -82,653 r270 top
R68 "4.99K" R0402 1045,433 r270 top
R69 "4.99K" R0402 1081,433 r270 top
R70 "4.99K" R0402 1595,433 r270 top
R71 "4.99K" R0402 1631,433 r270 top
R72 "4.99K" R0402 1140,-725 r180 top
R73 "4.99K" R0402 1343,-950 r270 top
R74 "4.99K" R0402 1018,-664 r0 bottom
R75 "4.99K" R0402 -325,-1035 r270 bottom
R76 "4.99K" R0402 -850,990 r90 bottom locked
R77 "4.99K" R0402 -1090,990 r90 bottom
R78 "6.34K" R0402 1307,-950 r90 top
R79 "6.34K" R0402 -1000,790 r180 bottom
R80 "13.3K" R0402 1240,-220 r90 top
R81 "13.3K" R0402 1045,-1295 r180 bottom
R82 "20.0K" R0402 -1635,586 r180 top
R83 "20.0K" R0402 -495,600 r90 top
R84 "20.0K" R0402 -735,-106 r180 top
R85 "20.0K" R0402 -735,-142 r180 top
R86 "20.0K" R0402 -645,-134 r0 top
R87 "20.0K" R0402 -625,-170 r0 top
R88 "20.0K" R0402 -446,-198 r90 top
R89 "20.0K" R0402 -446,-275 r270 top
R90 "20.0K" R0402 -620,-600 r0 top
R91 "20.0K" R0402 -550,-620 r90 top
R92 "20.0K" R0402 989,-1343 r90 bottom
R93 "31.6K" R0402 -1595,550 r180 top
R94 "162K" R0402 218,-1190 r270 top
R95 "301K" R0402 218,-1265 r270 top
R96 "301K" R0402 1070,-1350 r180 bottom
R97 "22.1K" R0402 835,-1300 r0 bottom
R98 "100K" R0402 1081,-165 r0 top
R99 "100K" R0402 1007,-404 r180 top
R100 "100K" R0402 1239.88,-354.15 r180 top
R101 "100K" R0402 1020,-725 r0 top
R102 "100K" R0402 1095,-960 r270 bottom
R103 "100K" R0402 1085,-1259 r180 bottom
R104 "100K" R0402 795,-1264 r0 bottom
R105 "115K" R0402 1155,-165 r0 top
R106 "150K" R0402 1185,-371 r90 top
R107 "150K" R0402 1040,-780 r90 top
R108 "200K" R0402 1024,-349 r270 top
R109 "56" R0603 -1120,920 r0 top
R110 "56" R0603 -1120,860 r0 top
R111 "56" R0603 -940,920 r0 top
R112 "56" R0603 -940,860 r0 top
R113 "56" R0603 -840,885 r90 bottom
R114 "56" R0603 -920,885 r90 bottom
R115 "56" R0603 -1020,885 r90 bottom
R116 "56" R0603 -1100,885 r90 bottom
R117 "0.015" R1206#3 -1585,-340 r180 top
R118 "0.015" R1206#4 -1535,-495 r270 top
RN1 "4.7K" RN-742C083 -595,560 r90 top
RN2 "4.7K" RN-742C083 -595,420 r90 top
SW1 "SWITCH-ROT16" SW-ROT-10MM-TH -1085,30 r0 top
TP1 "PAD" PAD25-SM 1400,-950 r0 bottom
TP2 "PAD" PAD25-SM 1400,-850 r270 bottom
TP3 "PAD" PAD25-SM 1300,-950 r270 bottom
TP4 "PAD" PAD25-SM 1300,-850 r180 bottom
TP5 "PAD" PAD25-SM 1200,-950 r270 bottom
TP6 "PAD" PAD25-SM 1200,-850 r270 bottom
TP7 "PAD" PAD25-SM 900,0 r180 bottom
TP8 "PAD" PAD25-SM 800,0 r180 bottom
TP9 "PAD" PAD25-SM 900,-100 r180 bottom
TP10 "PAD" PAD25-SM 800,-100 r270 bottom
TP11 "PAD" PAD25-SM 900,-200 r270 bottom
TP12 "PAD" PAD25-SM 800,-200 r270 bottom
TP13 "PAD" PAD25-SM 900,-300 r270 bottom
TP14 "PAD" PAD25-SM 800,-300 r270 bottom
U1 "XC7Z020-CLG400" BGA-400-08mm 0,0 r90 top locked
U2 "MT41K256M16" BGA-96-14X8MM -215,-725 r0 top
U3 "MT41K256M16" BGA-96-14X8MM 215,-725 r0 top
U4 "W25Q128" SOL-8 -575,-385 r0 top
U5 "TSB41AB2" PQFP-65 -1000,550 r90 top
U6 "TLVH431" SC70-6#1 -1615,695 r90 top
U7 "KC5032C24.5760C30E00" OSC-3x5MM -1435,355 r0 top
U8 "TXS0101" SC70-6#2 450,385 r90 top
U9 "74AUP2G17" SC70-6#2 450,480 r270 top
U10 "RTL8211F" QFN-40-5MM 810,325 r270 top
U11 "RTL8211F" QFN-40-5MM 1360,325 r270 top
U12 "LTC4210" SOT-23-6 -1605,-200 r180 top
U13 "LTC4210" SOT-23-6 -1415,-495 r0 top
U14 "LTC6902" MSOP-10 303,-1265 r0 top
U15 "LTC3644" BGA-36-08mm 1085,-580 r0 top
U16 "LTC3636" QFN-28-LTC3636 940,-1275 r0 top
U17 "LTC2908-B1" SOT-23-8 1125,-245 r90 top
U18 "LP2998" SO-9 15,-1240 r0 top
U19 "25MHz" OSC-2X2.5MM#1 1448,-83 r0 top
U20 "33.33MHz" OSC-2X2.5MM#2 -615,-40 r270 top

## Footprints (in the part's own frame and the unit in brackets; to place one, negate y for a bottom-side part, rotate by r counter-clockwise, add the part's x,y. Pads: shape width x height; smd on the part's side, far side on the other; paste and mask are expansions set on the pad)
BGA-36-08mm [mil]
  round 16 smd mask+2: A1(-78.74,78.74) A2(-47.24,78.74) A3(-15.75,78.74) A4(15.75,78.74) A5(47.24,78.74) A6(78.74,78.74) B1(-78.74,47.24) B2(-47.24,47.24) B3(-15.75,47.24) B4(15.75,47.24) B5(47.24,47.24) B6(78.74,47.24) C1(-78.74,15.75) C2(-47.24,15.75) C3(-15.75,15.75) C4(15.75,15.75) C5(47.24,15.75) C6(78.74,15.75) D1(-78.74,-15.75) D2(-47.24,-15.75) D3(-15.75,-15.75) D4(15.75,-15.75) D5(47.24,-15.75) D6(78.74,-15.75) E1(-78.74,-47.24) E2(-47.24,-47.24) E3(-15.75,-47.24) E4(15.75,-47.24) E5(47.24,-47.24) E6(78.74,-47.24) F1(-78.74,-78.74) F2(-47.24,-78.74) F3(-15.75,-78.74) F4(15.75,-78.74) F5(47.24,-78.74) F6(78.74,-78.74)
  silkscreen extent -112,-105 105,112, body extent -98,-98 98,98, height 67
BGA-96-14X8MM [mil]
  round 16 smd mask+2: A1(-125.98,236.22) A2(-94.49,236.22) A3(-62.99,236.22) A7(62.99,236.22) A8(94.49,236.22) A9(125.98,236.22) B1(-125.98,204.72) B2(-94.49,204.72) B3(-62.99,204.72) B7(62.99,204.72) B8(94.49,204.72) B9(125.98,204.72) C1(-125.98,173.23) C2(-94.49,173.23) C3(-62.99,173.23) C7(62.99,173.23) C8(94.49,173.23) C9(125.98,173.23) D1(-125.98,141.73) D2(-94.49,141.73) D3(-62.99,141.73) D7(62.99,141.73) D8(94.49,141.73) D9(125.98,141.73) E1(-125.98,110.24) E2(-94.49,110.24) E3(-62.99,110.24) E7(62.99,110.24) E8(94.49,110.24) E9(125.98,110.24) F1(-125.98,78.74) F2(-94.49,78.74) F3(-62.99,78.74) F7(62.99,78.74) F8(94.49,78.74) F9(125.98,78.74) G1(-125.98,47.24) G2(-94.49,47.24) G3(-62.99,47.24) G7(62.99,47.24) G8(94.49,47.24) G9(125.98,47.24) H1(-125.98,15.75) H2(-94.49,15.75) H3(-62.99,15.75) H7(62.99,15.75) H8(94.49,15.75) H9(125.98,15.75) J1(-125.98,-15.75) J2(-94.49,-15.75) J3(-62.99,-15.75) J7(62.99,-15.75) J8(94.49,-15.75) J9(125.98,-15.75) K1(-125.98,-47.24) K2(-94.49,-47.24) K3(-62.99,-47.24) K7(62.99,-47.24) K8(94.49,-47.24) K9(125.98,-47.24) L1(-125.98,-78.74) L2(-94.49,-78.74) L3(-62.99,-78.74) L7(62.99,-78.74) L8(94.49,-78.74) L9(125.98,-78.74) M1(-125.98,-110.24) M2(-94.49,-110.24) M3(-62.99,-110.24) M7(62.99,-110.24) M8(94.49,-110.24) M9(125.98,-110.24) N1(-125.98,-141.73) N2(-94.49,-141.73) N3(-62.99,-141.73) N7(62.99,-141.73) N8(94.49,-141.73) N9(125.98,-141.73) P1(-125.98,-173.23) P2(-94.49,-173.23) P3(-62.99,-173.23) P7(62.99,-173.23) P8(94.49,-173.23) P9(125.98,-173.23) R1(-125.98,-204.72) R2(-94.49,-204.72) R3(-62.99,-204.72) R7(62.99,-204.72) R8(94.49,-204.72) R9(125.98,-204.72) T1(-125.98,-236.22) T2(-94.49,-236.22) T3(-62.99,-236.22) T7(62.99,-236.22) T8(94.49,-236.22) T9(125.98,-236.22)
  silkscreen extent -190,-275 160,275, body extent -197,-276 197,276, height 43
BGA-400-08mm [mil]
  round 16 smd mask+2: A1(-299.21,299.21) A2(-267.72,299.21) A3(-236.22,299.21) A4(-204.72,299.21) A5(-173.23,299.21) A6(-141.73,299.21) A7(-110.24,299.21) A8(-78.74,299.21) A9(-47.24,299.21) A10(-15.75,299.21) A11(15.75,299.21) A12(47.24,299.21) A13(78.74,299.21) A14(110.24,299.21) A15(141.73,299.21) A16(173.23,299.21) A17(204.72,299.21) A18(236.22,299.21) A19(267.72,299.21) A20(299.21,299.21) B1(-299.21,267.72) B2(-267.72,267.72) B3(-236.22,267.72) B4(-204.72,267.72) B5(-173.23,267.72) B6(-141.73,267.72) B7(-110.24,267.72) B8(-78.74,267.72) B9(-47.24,267.72) B10(-15.75,267.72) B11(15.75,267.72) B12(47.24,267.72) B13(78.74,267.72) B14(110.24,267.72) B15(141.73,267.72) B16(173.23,267.72) B17(204.72,267.72) B18(236.22,267.72) B19(267.72,267.72) B20(299.21,267.72) C1(-299.21,236.22) C2(-267.72,236.22) C3(-236.22,236.22) C4(-204.72,236.22) C5(-173.23,236.22) C6(-141.73,236.22) C7(-110.24,236.22) C8(-78.74,236.22) C9(-47.24,236.22) C10(-15.75,236.22) C11(15.75,236.22) C12(47.24,236.22) C13(78.74,236.22) C14(110.24,236.22) C15(141.73,236.22) C16(173.23,236.22) C17(204.72,236.22) C18(236.22,236.22) C19(267.72,236.22) C20(299.21,236.22) D1(-299.21,204.72) D2(-267.72,204.72) D3(-236.22,204.72) D4(-204.72,204.72) D5(-173.23,204.72) D6(-141.73,204.72) D7(-110.24,204.72) D8(-78.74,204.72) D9(-47.24,204.72) D10(-15.75,204.72) D11(15.75,204.72) D12(47.24,204.72) D13(78.74,204.72) D14(110.24,204.72) D15(141.73,204.72) D16(173.23,204.72) D17(204.72,204.72) D18(236.22,204.72) D19(267.72,204.72) D20(299.21,204.72) E1(-299.21,173.23) E2(-267.72,173.23) E3(-236.22,173.23) E4(-204.72,173.23) E5(-173.23,173.23) E6(-141.73,173.23) E7(-110.24,173.23) E8(-78.74,173.23) E9(-47.24,173.23) E10(-15.75,173.23) E11(15.75,173.23) E12(47.24,173.23) E13(78.74,173.23) E14(110.24,173.23) E15(141.73,173.23) E16(173.23,173.23) E17(204.72,173.23) E18(236.22,173.23) E19(267.72,173.23) E20(299.21,173.23) F1(-299.21,141.73) F2(-267.72,141.73) F3(-236.22,141.73) F4(-204.72,141.73) F5(-173.23,141.73) F6(-141.73,141.73) F7(-110.24,141.73) F8(-78.74,141.73) F9(-47.24,141.73) F10(-15.75,141.73) F11(15.75,141.73) F12(47.24,141.73) F13(78.74,141.73) F14(110.24,141.73) F15(141.73,141.73) F16(173.23,141.73) F17(204.72,141.73) F18(236.22,141.73) F19(267.72,141.73) F20(299.21,141.73) G1(-299.21,110.24) G2(-267.72,110.24) G3(-236.22,110.24) G4(-204.72,110.24) G5(-173.23,110.24) G6(-141.73,110.24) G7(-110.24,110.24) G8(-78.74,110.24) G9(-47.24,110.24) G10(-15.75,110.24) G11(15.75,110.24) G12(47.24,110.24) G13(78.74,110.24) G14(110.24,110.24) G15(141.73,110.24) G16(173.23,110.24) G17(204.72,110.24) G18(236.22,110.24) G19(267.72,110.24) G20(299.21,110.24) H1(-299.21,78.74) H2(-267.72,78.74) H3(-236.22,78.74) H4(-204.72,78.74) H5(-173.23,78.74) H6(-141.73,78.74) H7(-110.24,78.74) H8(-78.74,78.74) H9(-47.24,78.74) H10(-15.75,78.74) H11(15.75,78.74) H12(47.24,78.74) H13(78.74,78.74) H14(110.24,78.74) H15(141.73,78.74) H16(173.23,78.74) H17(204.72,78.74) H18(236.22,78.74) H19(267.72,78.74) H20(299.21,78.74) J1(-299.21,47.24) J2(-267.72,47.24) J3(-236.22,47.24) J4(-204.72,47.24) J5(-173.23,47.24) J6(-141.73,47.24) J7(-110.24,47.24) J8(-78.74,47.24) J9(-47.24,47.24) J10(-15.75,47.24) J11(15.75,47.24) J12(47.24,47.24) J13(78.74,47.24) J14(110.24,47.24) J15(141.73,47.24) J16(173.23,47.24) J17(204.72,47.24) J18(236.22,47.24) J19(267.72,47.24) J20(299.21,47.24) K1(-299.21,15.75) K2(-267.72,15.75) K3(-236.22,15.75) K4(-204.72,15.75) K5(-173.23,15.75) K6(-141.73,15.75) K7(-110.24,15.75) K8(-78.74,15.75) K9(-47.24,15.75) K10(-15.75,15.75) K11(15.75,15.75) K12(47.24,15.75) K13(78.74,15.75) K14(110.24,15.75) K15(141.73,15.75) K16(173.23,15.75) K17(204.72,15.75) K18(236.22,15.75) K19(267.72,15.75) K20(299.21,15.75) L1(-299.21,-15.75) L2(-267.72,-15.75) L3(-236.22,-15.75) L4(-204.72,-15.75) L5(-173.23,-15.75) L6(-141.73,-15.75) L7(-110.24,-15.75) L8(-78.74,-15.75) L9(-47.24,-15.75) L10(-15.75,-15.75) L11(15.75,-15.75) L12(47.24,-15.75) L13(78.74,-15.75) L14(110.24,-15.75) L15(141.73,-15.75) L16(173.23,-15.75) L17(204.72,-15.75) L18(236.22,-15.75) L19(267.72,-15.75) L20(299.21,-15.75) M1(-299.21,-47.24) M2(-267.72,-47.24) M3(-236.22,-47.24) M4(-204.72,-47.24) M5(-173.23,-47.24) M6(-141.73,-47.24) M7(-110.24,-47.24) M8(-78.74,-47.24) M9(-47.24,-47.24) M10(-15.75,-47.24) M11(15.75,-47.24) M12(47.24,-47.24) M13(78.74,-47.24) M14(110.24,-47.24) M15(141.73,-47.24) M16(173.23,-47.24) M17(204.72,-47.24) M18(236.22,-47.24) M19(267.72,-47.24) M20(299.21,-47.24) N1(-299.21,-78.74) N2(-267.72,-78.74) N3(-236.22,-78.74) N4(-204.72,-78.74) N5(-173.23,-78.74) N6(-141.73,-78.74) N7(-110.24,-78.74) N8(-78.74,-78.74) N9(-47.24,-78.74) N10(-15.75,-78.74) N11(15.75,-78.74) N12(47.24,-78.74) N13(78.74,-78.74) N14(110.24,-78.74) N15(141.73,-78.74) N16(173.23,-78.74) N17(204.72,-78.74) N18(236.22,-78.74) N19(267.72,-78.74) N20(299.21,-78.74) P1(-299.21,-110.24) P2(-267.72,-110.24) P3(-236.22,-110.24) P4(-204.72,-110.24) P5(-173.23,-110.24) P6(-141.73,-110.24) P7(-110.24,-110.24) P8(-78.74,-110.24) P9(-47.24,-110.24) P10(-15.75,-110.24) P11(15.75,-110.24) P12(47.24,-110.24) P13(78.74,-110.24) P14(110.24,-110.24) P15(141.73,-110.24) P16(173.23,-110.24) P17(204.72,-110.24) P18(236.22,-110.24) P19(267.72,-110.24) P20(299.21,-110.24) R1(-299.21,-141.73) R2(-267.72,-141.73) R3(-236.22,-141.73) R4(-204.72,-141.73) R5(-173.23,-141.73) R6(-141.73,-141.73) R7(-110.24,-141.73) R8(-78.74,-141.73) R9(-47.24,-141.73) R10(-15.75,-141.73) R11(15.75,-141.73) R12(47.24,-141.73) R13(78.74,-141.73) R14(110.24,-141.73) R15(141.73,-141.73) R16(173.23,-141.73) R17(204.72,-141.73) R18(236.22,-141.73) R19(267.72,-141.73) R20(299.21,-141.73) T1(-299.21,-173.23) T2(-267.72,-173.23) T3(-236.22,-173.23) T4(-204.72,-173.23) T5(-173.23,-173.23) T6(-141.73,-173.23) T7(-110.24,-173.23) T8(-78.74,-173.23) T9(-47.24,-173.23) T10(-15.75,-173.23) T11(15.75,-173.23) T12(47.24,-173.23) T13(78.74,-173.23) T14(110.24,-173.23) T15(141.73,-173.23) T16(173.23,-173.23) T17(204.72,-173.23) T18(236.22,-173.23) T19(267.72,-173.23) T20(299.21,-173.23) U1(-299.21,-204.72) U2(-267.72,-204.72) U3(-236.22,-204.72) U4(-204.72,-204.72) U5(-173.23,-204.72) U6(-141.73,-204.72) U7(-110.24,-204.72) U8(-78.74,-204.72) U9(-47.24,-204.72) U10(-15.75,-204.72) U11(15.75,-204.72) U12(47.24,-204.72) U13(78.74,-204.72) U14(110.24,-204.72) U15(141.73,-204.72) U16(173.23,-204.72) U17(204.72,-204.72) U18(236.22,-204.72) U19(267.72,-204.72) U20(299.21,-204.72) V1(-299.21,-236.22) V2(-267.72,-236.22) V3(-236.22,-236.22) V4(-204.72,-236.22) V5(-173.23,-236.22) V6(-141.73,-236.22) V7(-110.24,-236.22) V8(-78.74,-236.22) V9(-47.24,-236.22) V10(-15.75,-236.22) V11(15.75,-236.22) V12(47.24,-236.22) V13(78.74,-236.22) V14(110.24,-236.22) V15(141.73,-236.22) V16(173.23,-236.22) V17(204.72,-236.22) V18(236.22,-236.22) V19(267.72,-236.22) V20(299.21,-236.22) W1(-299.21,-267.72) W2(-267.72,-267.72) W3(-236.22,-267.72) W4(-204.72,-267.72) W5(-173.23,-267.72) W6(-141.73,-267.72) W7(-110.24,-267.72) W8(-78.74,-267.72) W9(-47.24,-267.72) W10(-15.75,-267.72) W11(15.75,-267.72) W12(47.24,-267.72) W13(78.74,-267.72) W14(110.24,-267.72) W15(141.73,-267.72) W16(173.23,-267.72) W17(204.72,-267.72) W18(236.22,-267.72) W19(267.72,-267.72) W20(299.21,-267.72) Y1(-299.21,-299.21) Y2(-267.72,-299.21) Y3(-236.22,-299.21) Y4(-204.72,-299.21) Y5(-173.23,-299.21) Y6(-141.73,-299.21) Y7(-110.24,-299.21) Y8(-78.74,-299.21) Y9(-47.24,-299.21) Y10(-15.75,-299.21) Y11(15.75,-299.21) Y12(47.24,-299.21) Y13(78.74,-299.21) Y14(110.24,-299.21) Y15(141.73,-299.21) Y16(173.23,-299.21) Y17(204.72,-299.21) Y18(236.22,-299.21) Y19(267.72,-299.21) Y20(299.21,-299.21)
  silkscreen extent -360,-335 335,335
C0201 [mil]
  rrect16% 10x12 smd paste+1.5 mask+2: 1(-10,0) 2(10,0)
  silkscreen extent -22,-13 22,13, body extent -10,-5 10,5, height 10
C0402 [mil]
  rrect15% 20x22 smd mask+2: 1(-20,0) 2(20,0)
  silkscreen extent -37,-18 37,18, body extent -20,-10 20,10, height 20
C0603 [mil]
  rect 30x30 smd mask+2: 1(-30,0) 2(30,0)
  silkscreen extent -55,-30 55,30, body extent -30,-15 30,15, height 24
C0805 [mil]
  rrect15% 30x50 smd mask+2: 1(-40,0) 2(40,0)
  silkscreen extent -65,-35 65,35, body extent -40,-25 40,25, height 40
C1206 [mil]
  rrect12% 55x65 smd mask+2: 1(-55,0) 2(55,0)
  silkscreen extent -90,-45 90,45, body extent -69,-32 69,32, height 54
C1210 [mil]
  rrect10% 55x105 smd mask+2: 1(-55,0) 2(55,0)
  silkscreen extent -90,-60 90,60, body extent -69,-53 69,53, height 87
CAP-D-31 [mil]
  rrect5% 110x120 smd paste-60 mask+2: 1(-120,0) 2(120,0)
  silkscreen extent -155,-90 155,90, body extent -148,-91 148,91, height 126
CAP-D-43 [mil]
  rrect5% 110x120 smd paste-60 mask+2: 1(-120,0) 2(120,0)
  silkscreen extent -155,-90 155,90, body extent -148,-91 148,91, height 173
CB0402 [mil]
  rrect15% 20x22 smd mask+2: 1(-20,0) 2(20,0)
  silkscreen extent -37,-18 37,18, body extent -20,-10 20,10, height 20
CB0603 [mil]
  rrect10% 30x30 smd mask+2: 1(-30,0) 2(30,0)
  silkscreen extent -55,-30 55,30, body extent -30,-15 30,15, height 24
CONN-RJ-45-DUAL-PULSE-JXD0-2015NL [mil] "Pulse Engineering: JXD0-2015NL"
  oval 52x85 / inner oval 52x85 / far side oval 60x90 hole 32 slot 65 at 90 deg: 1(607.5,120) 2(-607.5,120)
  round 55 / inner round 55 / far side round 50 hole 35: 1A(50,350)
  round 55 / inner round 55 / far side round 60 hole 35: 1B(-500,350) 2A(100,250) 2B(-450,250) 3A(150,350) 3B(-400,350) 4A(200,250) 4B(-350,250) 5A(250,350) 5B(-300,350) 6A(300,250) 6B(-250,250) 7A(350,350) 7B(-200,350) 8A(400,250) 8B(-150,250) 9A(450,350) 9B(-100,350) 10A(500,250) 10B(-50,250)
  oval 85x52 / inner oval 85x52 / far side oval 80x52 hole 32 slot 65 at 0 deg: 3(0,412.5)
  round 128 hole 128: 5(-500,0) 6(500,0)
  round 60 / inner round 60 / far side round 58 hole 40: 11A(20,-90) 14B(-20,-160)
  round 60 / inner round 60 / far side round 70 hole 40: 11B(-530,-160) 12A(120,-90) 12B(-430,-160) 13A(430,-160) 13B(-120,-160) 14A(530,-160)
  silkscreen extent -615,-320 615,415, body extent -679,-419 684,421, height 600
CONN-uSD-JAE-ST12S0 [mil] "JAE: ST12S010VBAR1800"
  rrect20% 25x40 smd mask+2: 1(90,594.17) 2(54.57,594.17) 3(19.13,594.17) 4(-16.3,594.17) 5(-51.73,594.17) 6(-87.17,594.17) 7(-122.6,594.17) 8(-158.03,594.17)
  rrect20% 40x34 smd mask+2: 9(274,127.97) 10(-275,128.97) 11(-275,204.72)
  rrect20% 36x40 smd mask+2: 12(-219.06,594.17)
  rrect20% 40x67 smd mask+2: 13(-280,580.67) 14(280,580.67)
  rrect20% 33x56 smd mask+2: 15(270.5,427.17) 16(270.5,212.67)
  rrect20% 36x67 smd mask+2: 17(280,41.34) 18(-280,41.34)
  rrect20% 37x56 smd mask+2: 19(-277.5,320.87)
  Top Layer keep-out region: -245.08,59.17 160,59.17 160,149.17 -245.08,149.17
  Top Layer keep-out region: -235.06,462.13 104.94,462.13 104.94,544.3 -235.06,544.3
  Top Layer keep-out region: -235.08,144.17 105,144.17 105,304.17 -235.08,304.17
  Top Layer keep-out region: -250,292.17 140,292.17 140,469.17 -250,469.17
  silkscreen extent -270,5 270,602, body extent -287,-5 287,597, height 54
DIODE-SMC [mil]
  rect 100x140 smd mask+2: 1(-130,0) 2(130,0)
  silkscreen extent -180,-125 180,125, body extent -152,-110 152,110, height 103
FIREWIRE6-RA [mil]
  round 57 / inner round 52 / far side round 65 hole 32 mask+2: 1(59.06,78.74) 2(-59.06,78.74) 3(59.06,157.48) 4(-59.06,157.48) 5(59.06,236.22) 6(-59.06,236.22)
  oval 70x135 / inner oval 64x125 / far side oval 80x135 hole 40 slot 84 at 90 deg copper offset 2,-10: 7(-145.73,257.87)
  oval 70x135 / inner oval 64x125 / far side oval 80x135 hole 40 slot 84 at 90 deg copper offset -2,-10: 8(145.73,257.87)
  oval 110x65 / inner oval 110x52 / far side oval 120x80 hole 32 slot 80 at 0 deg mask+2: 9(0,0)
  silkscreen extent -165,0 165,170, body extent -175,-8 175,700, height 516
HDR-2x1-100 [mil] "AMP 0.100"
  round 65 / inner round 60 / far side round 75 hole 40: 1(-50,0)
  round 65 / inner round 60 / far side oval 60x75 hole 40: 2(50,0)
  silkscreen extent -100,-115 100,115
HDR-3x2-2MM [mil]
  round 57 / inner round 52 / far side round 60 hole 32: 1(-78.74,39.37) 2(-78.74,-39.37) 3(0,39.37) 4(0,-39.37) 5(78.74,39.37) 6(78.74,-39.37)
  silkscreen extent -155,-320 155,55
HDR-6x1-100 [mil] "AMP: 3-641215-6"
  round 65 / inner round 60 / far side round 75 hole 40: 1(-250,0) 2(-150,0) 3(-50,0) 4(50,0) 5(150,0) 6(250,0)
  silkscreen extent -300,-50 300,50
HDR-7x2-2MM [mil]
  round 57 / inner round 52 / far side round 60 hole 32: 1(-236.22,-39.37) 2(-236.22,39.37) 3(-157.48,-39.37) 4(-157.48,39.37) 5(-78.74,-39.37) 6(-78.74,39.37) 7(0,-39.37) 8(0,39.37) 9(78.74,-39.37) 10(78.74,39.37) 11(157.48,-39.37) 12(157.48,39.37) 13(236.22,-39.37) 14(236.22,39.37)
  silkscreen extent -320,-160 320,115
HDR-22x2-2MM [mil]
  round 65 / inner round 52 / far side round 57 hole 32: 1(-826.77,39.37) 2(-826.77,-39.37) 3(-748.03,39.37) 4(-748.03,-39.37) 5(-669.29,39.37) 6(-669.29,-39.37) 7(-590.55,39.37) 8(-590.55,-39.37) 9(-511.81,39.37) 10(-511.81,-39.37) 11(-433.07,39.37) 12(-433.07,-39.37) 13(-354.33,39.37) 14(-354.33,-39.37) 15(-275.59,39.37) 16(-275.59,-39.37) 17(-196.85,39.37) 18(-196.85,-39.37) 19(-118.11,39.37) 20(-118.11,-39.37) 21(-39.37,39.37) 22(-39.37,-39.37) 23(39.37,39.37) 24(39.37,-39.37) 25(118.11,39.37) 26(118.11,-39.37) 27(196.85,39.37) 28(196.85,-39.37) 29(275.59,39.37) 30(275.59,-39.37) 31(354.33,39.37) 32(354.33,-39.37) 33(433.07,39.37) 34(433.07,-39.37) 35(511.81,39.37) 36(511.81,-39.37) 37(590.55,39.37) 38(590.55,-39.37) 39(669.29,39.37) 40(669.29,-39.37) 41(748.03,39.37) 42(748.03,-39.37) 43(826.77,39.37) 44(826.77,-39.37)
  silkscreen extent -866,-70 709,79
INDUCTOR-EPL2014 [mil]
  rect 40x90 smd: 1(-28,0) 2(28,0)
  silkscreen extent -45,-53 45,53, body extent -43,-43 43,43, height 57
INDUCTOR-XAL4040 [mil] "Coilcraft: XAL40xx Seriese, also XFL4020"
  rrect25% 160x50 smd paste-30 mask+2: 1(0,-50) 2(0,50)
  silkscreen extent -85,-85 85,85, body extent -85,-85 85,85, height 161
INDUCTOR-XGL5030 [mil] "Coilcraft: XGL5030"
  rrect10% 185x50 smd paste-30 mask+2: 1(0,-65) 2(0,65)
  silkscreen extent -112,-108 112,108, body extent -108,-108 108,108, height 132
L0402 [mil]
  rrect15% 20x22 smd mask+2: 1(-20,0) 2(20,0)
  silkscreen extent -37,-18 37,18, body extent -20,-10 20,10, height 20
L0603 [mil]
  rrect10% 30x30 smd mask+2: 1(-30,0) 2(30,0)
  silkscreen extent -55,-30 55,30, body extent -30,-15 30,15, height 24
LED-0805 [mil]
  rect 50x50 smd mask+2: 1(-42,0) 2(42,0)
  silkscreen extent -67,-43 66,35
MHOLE4 [mil]
  round 225 / inner round 160 / far side round 290 hole 120: 1(0,0)
MSOP-10 [mil]
  rrect12% 11x55 smd mask+1: 1(-39.37,-92.5) 2(-19.69,-92.5) 3(0,-92.5) 4(19.68,-92.5) 5(39.37,-92.5) 6(39.37,92.5) 7(19.68,92.5) 8(0,92.5) 9(-19.69,92.5) 10(-39.37,92.5)
  silkscreen extent -65,-90 60,55, body extent -59,-96 59,96, height 43
OSC-2X2.5MM#1 [mil] "TXC Corp: 8W-24.000MBB-T"
  rrect10% 40x40 smd mask+2: 1(-36,-31) 2(36,-31) 3(36,31) 4(-36,31)
  silkscreen extent -53,-70 50,40, body extent -50,-40 48,39, height 31
OSC-2X2.5MM#2 [mil] "TXC Corp: 8W-24.000MBB-T"
  rect 40x45 smd mask+2: 1(-36,-33) 2(36,-33) 3(36,33) 4(-36,33)
  silkscreen extent -69,-43 50,40, body extent -50,-40 48,39, height 31
OSC-3x5MM [mil] "ECS-3525-200AN"
  rect 65x60 smd mask+2: 1(-50,-46) 2(50,-46) 3(50,46) 4(-50,46)
  silkscreen extent -100,-73 100,65
PAD25-SM [mil]
  round 50 smd paste-99999 mask+4: 1(0,0)
POWERPAK-1212#1 [mil] "Also: Power33"
  rect 16x50 smd mask+2: 1(-38.39,-60) 2(-12.8,-60) 3(12.8,-60)
  rect 16.5x50 smd mask+2: 4(38.39,-60)
  rect 95x100 smd mask+2: 5(0,35)
  Top Layer region: 67,8 45,8 45,-15 67,-15
  Top Layer region: -67,-15 -45,-15 -45,8 -67,8
  silkscreen extent -69,-89 67,67, body extent -66,-70 66,70, height 44
POWERPAK-1212#2 [mil] "Also: Power33"
  rect 16.5x50 smd mask+2: 1(-38.39,-60) 2(-12.8,-60) 3(12.8,-60) 4(38.39,-60)
  rect 95x100 smd mask+2: 5(0,35)
  Top Layer region: 67,8 45,8 45,-15 67,-15
  Top Layer region: -67,-15 -45,-15 -45,8 -67,8
  silkscreen extent -69,-89 67,67, body extent -66,-70 66,70, height 44
PQFP-65 [mil]
  rrect27% 62x11 smd mask+1: 1(-225,147.64) 2(-225,127.95) 3(-225,108.27) 4(-225,88.58) 5(-225,68.9) 6(-225,49.21) 7(-225,29.53) 8(-225,9.84) 9(-225,-9.84) 10(-225,-29.53) 11(-225,-49.21) 12(-225,-68.9) 13(-225,-88.58) 14(-225,-108.27) 15(-225,-127.95) 16(-225,-147.64) 33(225,-147.64) 34(225,-127.95) 35(225,-108.27) 36(225,-88.58) 37(225,-68.9) 38(225,-49.21) 39(225,-29.53) 40(225,-9.84) 41(225,9.84) 42(225,29.53) 43(225,49.21) 44(225,68.9) 45(225,88.58) 46(225,108.27) 47(225,127.95) 48(225,147.64)
  rrect27% 11x62 smd mask+1: 17(-147.64,-225) 18(-127.95,-225) 19(-108.27,-225) 20(-88.58,-225) 21(-68.9,-225) 22(-49.21,-225) 23(-29.53,-225) 24(-9.84,-225) 25(9.84,-225) 26(29.53,-225) 27(49.21,-225) 28(68.9,-225) 29(88.58,-225) 30(108.27,-225) 31(127.95,-225) 32(147.64,-225) 49(147.64,225) 50(127.95,225) 51(108.27,225) 52(88.58,225) 53(68.9,225) 54(49.21,225) 55(29.53,225) 56(9.84,225) 57(-9.84,225) 58(-29.53,225) 59(-49.21,225) 60(-68.9,225) 61(-88.58,225) 62(-108.27,225) 63(-127.95,225) 64(-147.64,225)
  rrect4% 220x220 smd paste-120 mask+1: 65(0,0)
  silkscreen extent -280,-280 280,280
QFN-28-LTC3636 [mil]
  rrect20% 11x32 smd mask+2: 1(-68.9,-77) 2(-49.21,-77) 3(-29.53,-77) 4(-9.84,-77) 5(9.84,-77) 6(29.53,-77) 7(49.21,-77) 8(68.9,-77) 15(68.9,77) 16(49.21,77) 17(29.53,77) 18(9.84,77) 19(-9.84,77) 20(-29.53,77) 21(-49.21,77) 22(-68.9,77)
  rrect20% 32x11 smd mask+2: 9(97,-49.21) 10(97,-29.53) 11(97,-9.84) 12(97,9.84) 13(97,29.53) 14(97,49.21) 23(-97,49.21) 24(-97,29.53) 25(-97,9.84) 26(-97,-9.84) 27(-97,-29.53) 28(-97,-49.21)
  rrect20% 9x11 smd paste-5 mask+2: 29(7.5,-39.37)
  rrect20% 22x10 smd paste-6 mask+2: 30(-22,-1) 31(22,-1)
  round 11 smd paste-1.75 mask+2: 32(0,18.5) 33(-41.5,22) 34(41.5,22)
  silkscreen extent -100,-99 100,80, body extent -99,-79 99,79, height 30
QFN-40-5MM [mil]
  rrect20% 30x8 smd mask+2: 1(-97,70.87) 2(-97,55.12) 3(-97,39.37) 4(-97,23.62) 5(-97,7.87) 6(-97,-7.87) 7(-97,-23.62) 8(-97,-39.37) 9(-97,-55.12) 10(-97,-70.87) 21(97,-70.87) 22(97,-55.12) 23(97,-39.37) 24(97,-23.62) 25(97,-7.87) 26(97,7.87) 27(97,23.62) 28(97,39.37) 29(97,55.12) 30(97,70.87)
  rrect20% 8x30 smd mask+2: 11(-70.87,-97) 12(-55.12,-97) 13(-39.37,-97) 14(-23.62,-97) 15(-7.87,-97) 16(7.87,-97) 17(23.62,-97) 18(39.37,-97) 19(55.12,-97) 20(70.87,-97) 31(70.87,97) 32(55.12,97) 33(39.37,97) 34(23.62,97) 35(7.87,97) 36(-7.87,97) 37(-23.62,97) 38(-39.37,97) 39(-55.12,97) 40(-70.87,97)
  rrect2% 146x146 smd paste-75 mask+2: 41(0,0)
  silkscreen extent -136,-136 136,136, body extent -138,-138 138,138, height 33
R0201 [mil]
  rrect16% 10x12 smd paste+1.5 mask+2: 1(-10,0) 2(10,0)
  silkscreen extent -22,-13 22,13, body extent -10,-5 10,5, height 10
R0402 [mil]
  rrect15% 20x22 smd mask+2: 1(-20,0) 2(20,0)
  silkscreen extent -37,-18 37,18, body extent -20,-10 20,10, height 20
R0603 [mil]
  rect 30x30 smd mask+2: 1(-30,0) 2(30,0)
  silkscreen extent -55,-30 55,30, body extent -30,-15 30,15, height 25
R1206#1 [mil]
  rrect10% 55x66 smd mask+2: 1(-55,0)
  rrect10% 55x65 smd mask+2: 2(55,0)
  silkscreen extent -90,-45 90,45, body extent -60,-30 60,30, height 35
R1206#2 [mil]
  rrect10% 55x65 smd mask+2: 1(-55,0) 2(55,0)
  silkscreen extent -90,-45 90,45, body extent -60,-30 60,30, height 35
R1206#3 [mil]
  rect 55x65 smd mask+2: 1(-55,0) 2(55,0)
  silkscreen extent -90,-45 90,45, body extent -60,-30 60,30, height 35
R1206#4 [mil]
  rect 55x65 smd mask+2: 1(-55,0)
  rect 54x65 smd mask+2: 2(55,0)
  silkscreen extent -90,-45 90,45, body extent -60,-30 60,30, height 35
RN-742C083 [mil]
  rect 20x36 smd mask+1: 1(-47.24,-35.5) 2(-15.75,-35.5) 3(15.75,-35.5) 4(47.24,-35.5) 5(47.24,35.5) 6(15.75,35.5) 7(-15.75,35.5) 8(-47.24,35.5)
  silkscreen extent -64,-32 64,32, body extent -67,-35 67,36, height 28
SC70-6#1 [mil] "SC70-6, SOT-363"
  rect 15x40 smd mask+2: 1(-25.59,-37.5) 2(0,-37.5) 3(25.59,-37.5) 4(25.59,37.5) 5(0,37.5) 6(-25.59,37.5)
  silkscreen extent -45,-82 45,25, body extent -42,-47 42,47, height 43
SC70-6#2 [mil] "SC70-6, SOT-363"
  rrect20% 15x32 smd mask+2: 1(-25.59,-39) 2(0,-39) 3(25.59,-39) 4(25.59,39) 5(0,39) 6(-25.59,39)
  silkscreen extent -57,-47 45,25, body extent -42,-47 42,47, height 43
SC70-6-NP [mil] "SC70-6, SOT-363"
  rrect20% 15x32 smd mask+2: 1(-25.59,-39) 2(0,-39) 3(25.59,-39) 4(25.59,39) 5(0,39) 6(-25.59,39)
  silkscreen extent -45,-25 45,25, body extent -42,-47 42,47, height 43
SO-9 [mil]
  rrect60% 24x60 smd mask+3: 1(-75,-105) 2(-25,-105) 3(25,-105) 4(75,-105)
  rrect50% 24x60 smd mask+3: 5(75,105) 6(25,105) 7(-25,105) 8(-75,105)
  rrect5% 150x100 smd paste-16: 9(0,0)
  silkscreen extent -108,-83 100,60, body extent -98,-122 98,122, height 69
SOL-8 [mil]
  rrect20% 24x70 smd: 1(-75,-140) 2(-25,-140) 3(25,-140) 4(75,-140) 5(75,140) 6(25,140) 7(-25,140) 8(-75,140)
  silkscreen extent -105,-85 105,85, body extent -104,-147 104,147, height 69
SOT-23-6 [mil]
  rect 25x50 smd mask+2: 1(-37.5,-50) 2(0,-50) 3(37.5,-50) 4(37.5,50) 5(0,50) 6(-37.5,50)
  silkscreen extent -74,-47 60,35, body extent -59,-59 59,59, height 57
SOT-23-8 [mil]
  rrect20% 16x46 smd mask+2: 1(-38.39,-52) 2(-12.8,-52) 3(12.8,-52) 4(38.39,-52) 5(38.39,52) 6(12.8,52) 7(-12.8,52) 8(-38.39,52)
  silkscreen extent -74,-47 60,35, body extent -59,-59 59,59, height 57
SOT-89 [mil]
  rect 36x55 smd mask+2: 1(-60,-62.5) 2(60,-62.5)
  rect 36x180 smd paste-20 mask+2: 3(0,0)
  Top Layer region: -35,-20 35,-20 35,90 -35,90
  silkscreen extent -90,-40 90,60, body extent -89,-79 89,79, height 59
SOT-523 [mil] "Also SC-75, SOT-416"
  rect 15x24 smd mask+2: 1(-20,-27) 2(20,-27) 3(0,27)
  silkscreen extent -34,-20 34,20, body extent -33,-32 33,32, height 31
SW-ROT-10MM-TH [mil] "Grauhill 94H seriese"
  round 65 / inner round 52 / far side round 57 hole 32 mask+2: 1(-100,-150) 2(0,-150) 3(100,-150) 4(100,150) 5(0,150) 6(-100,150)
  silkscreen extent -200,-200 200,200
